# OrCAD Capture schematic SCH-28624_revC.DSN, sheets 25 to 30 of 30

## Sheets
25 25 Core Pwr: size B
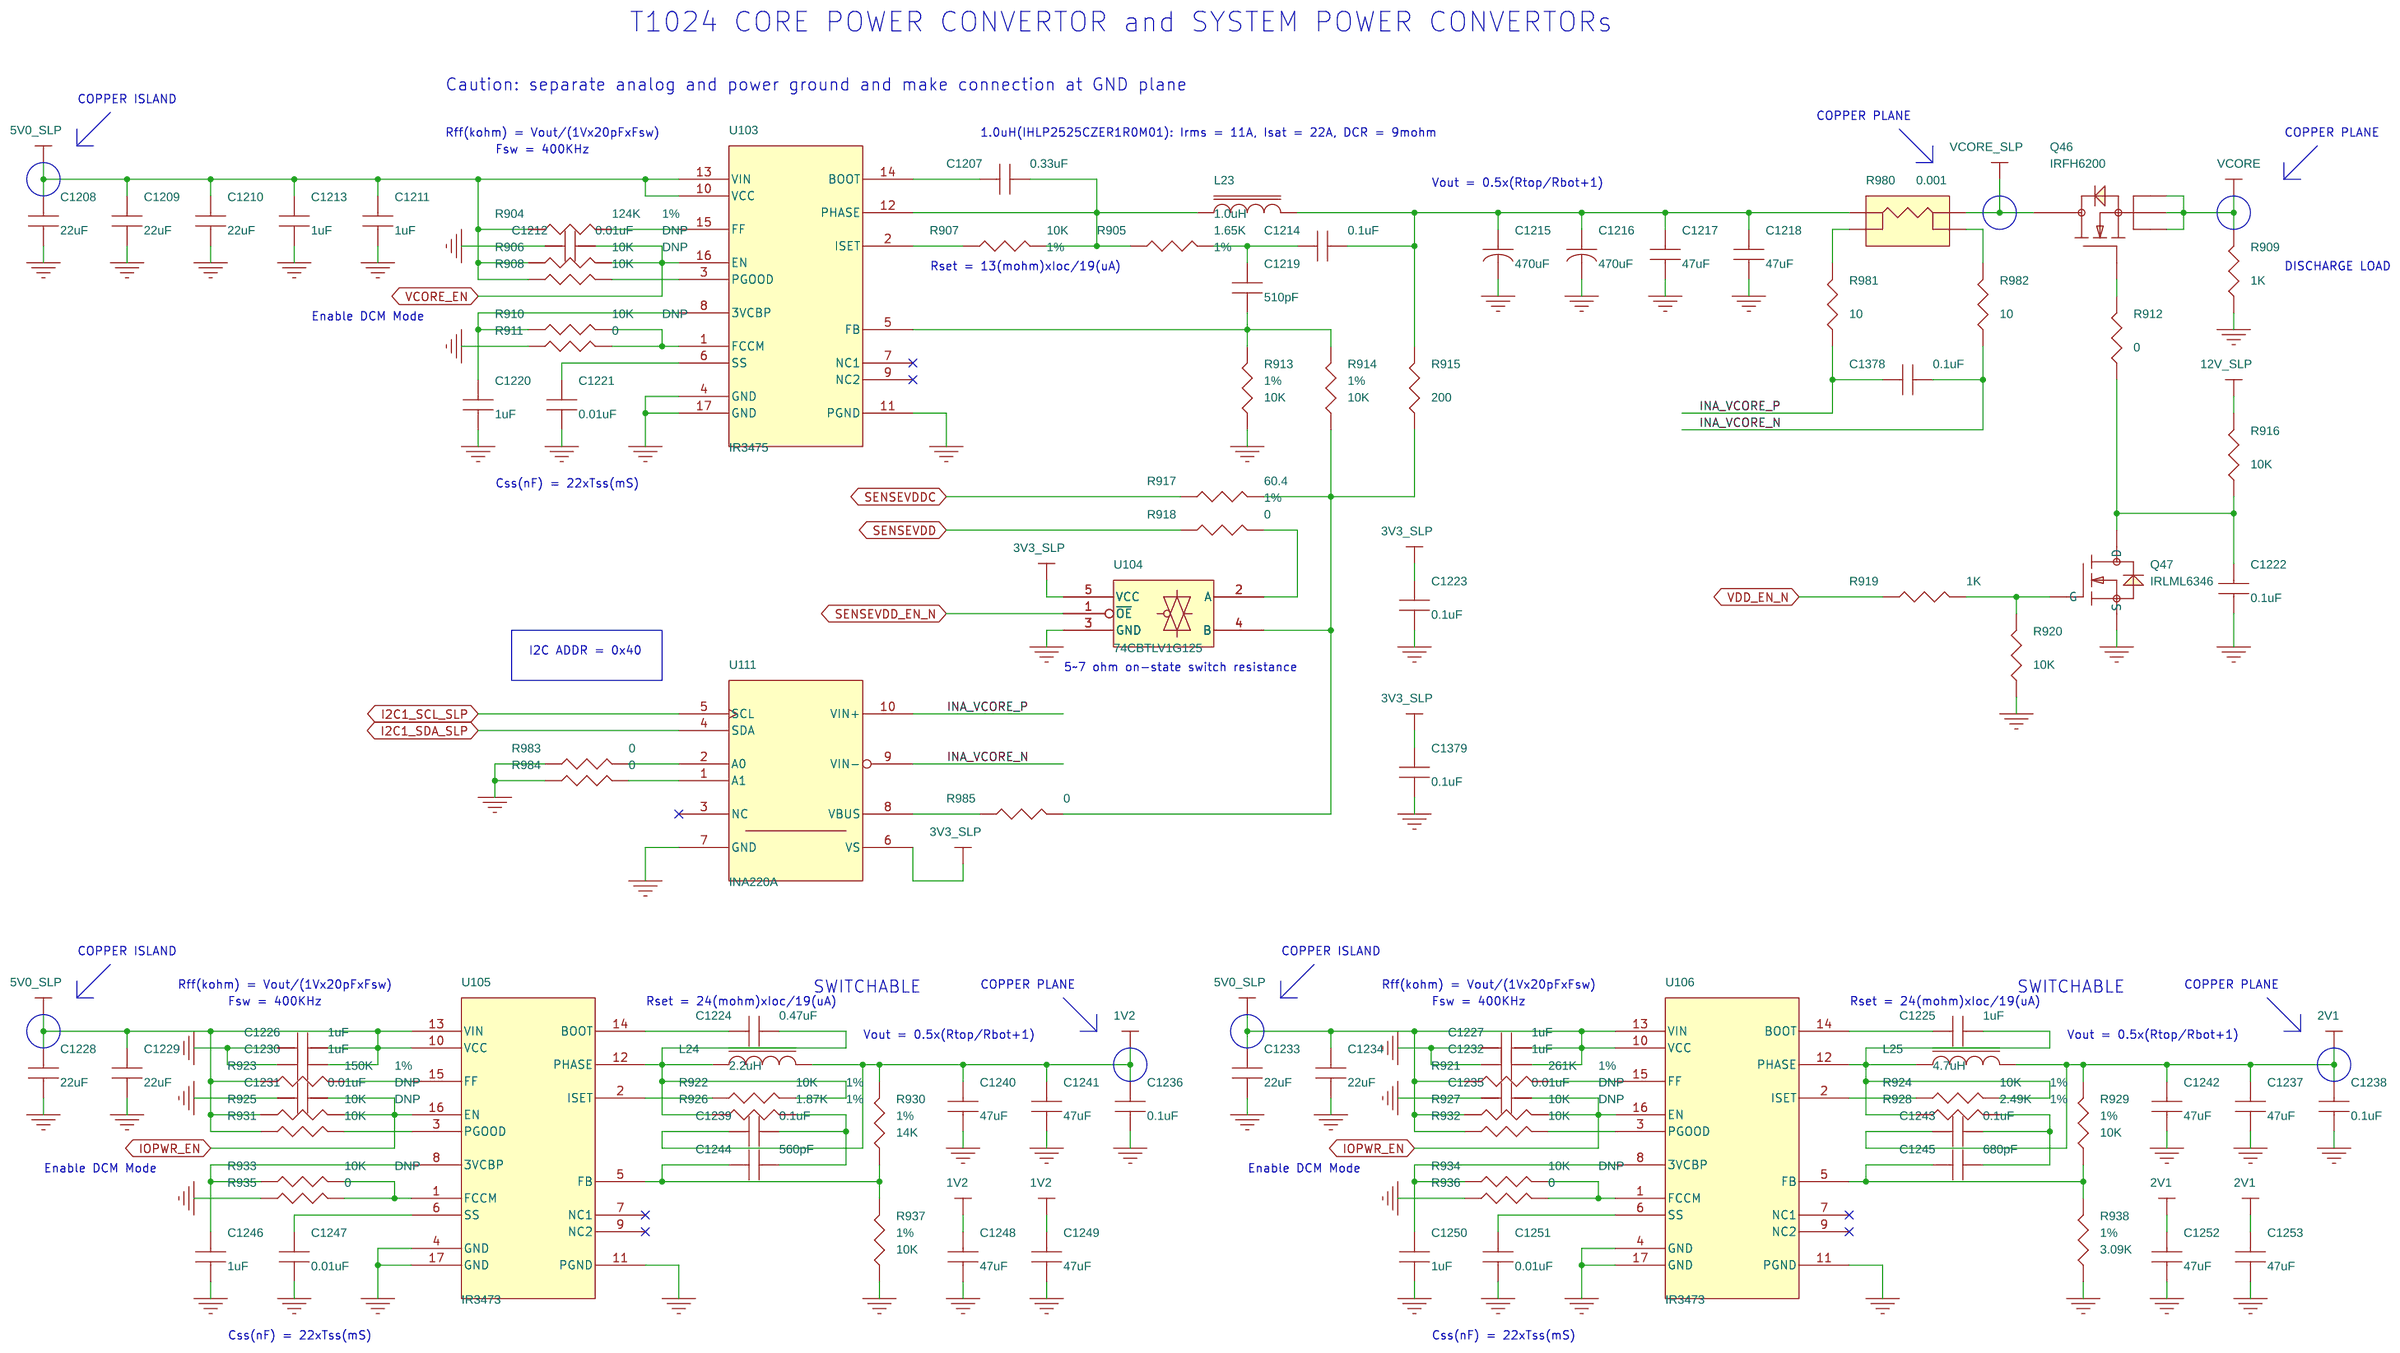
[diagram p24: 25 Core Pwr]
26 26 Other Pwr: size B
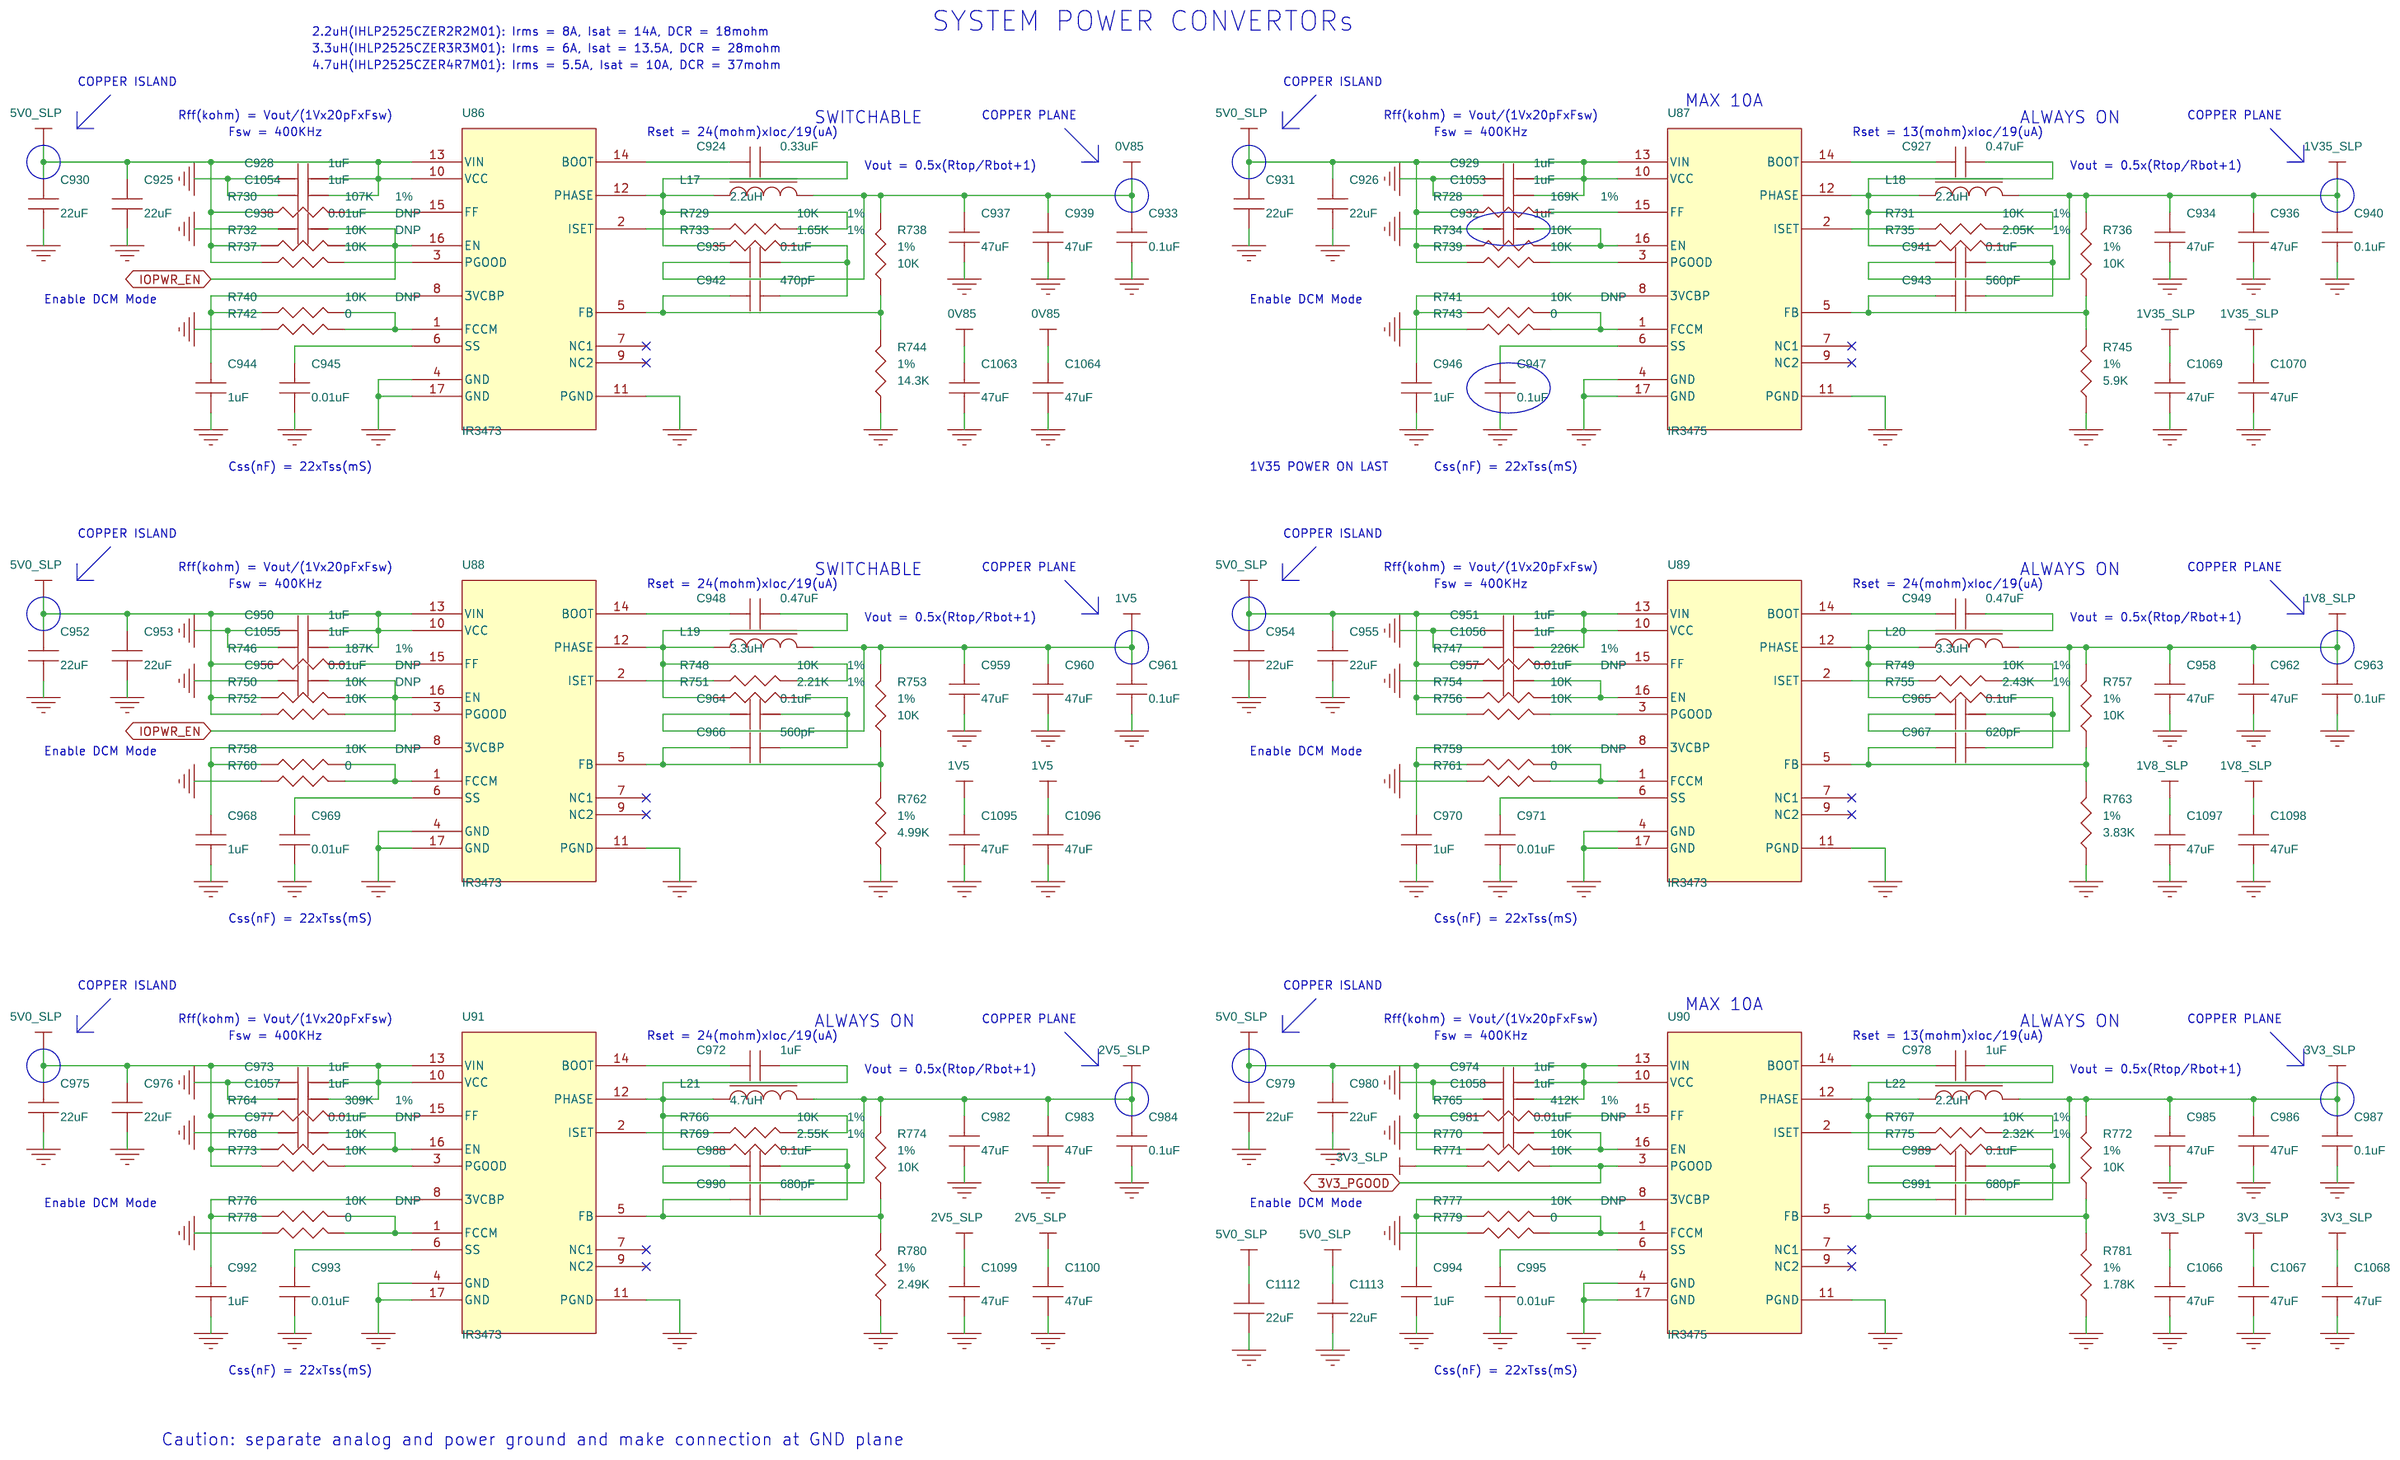
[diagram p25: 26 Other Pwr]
27 27 Pwr Switch: size B
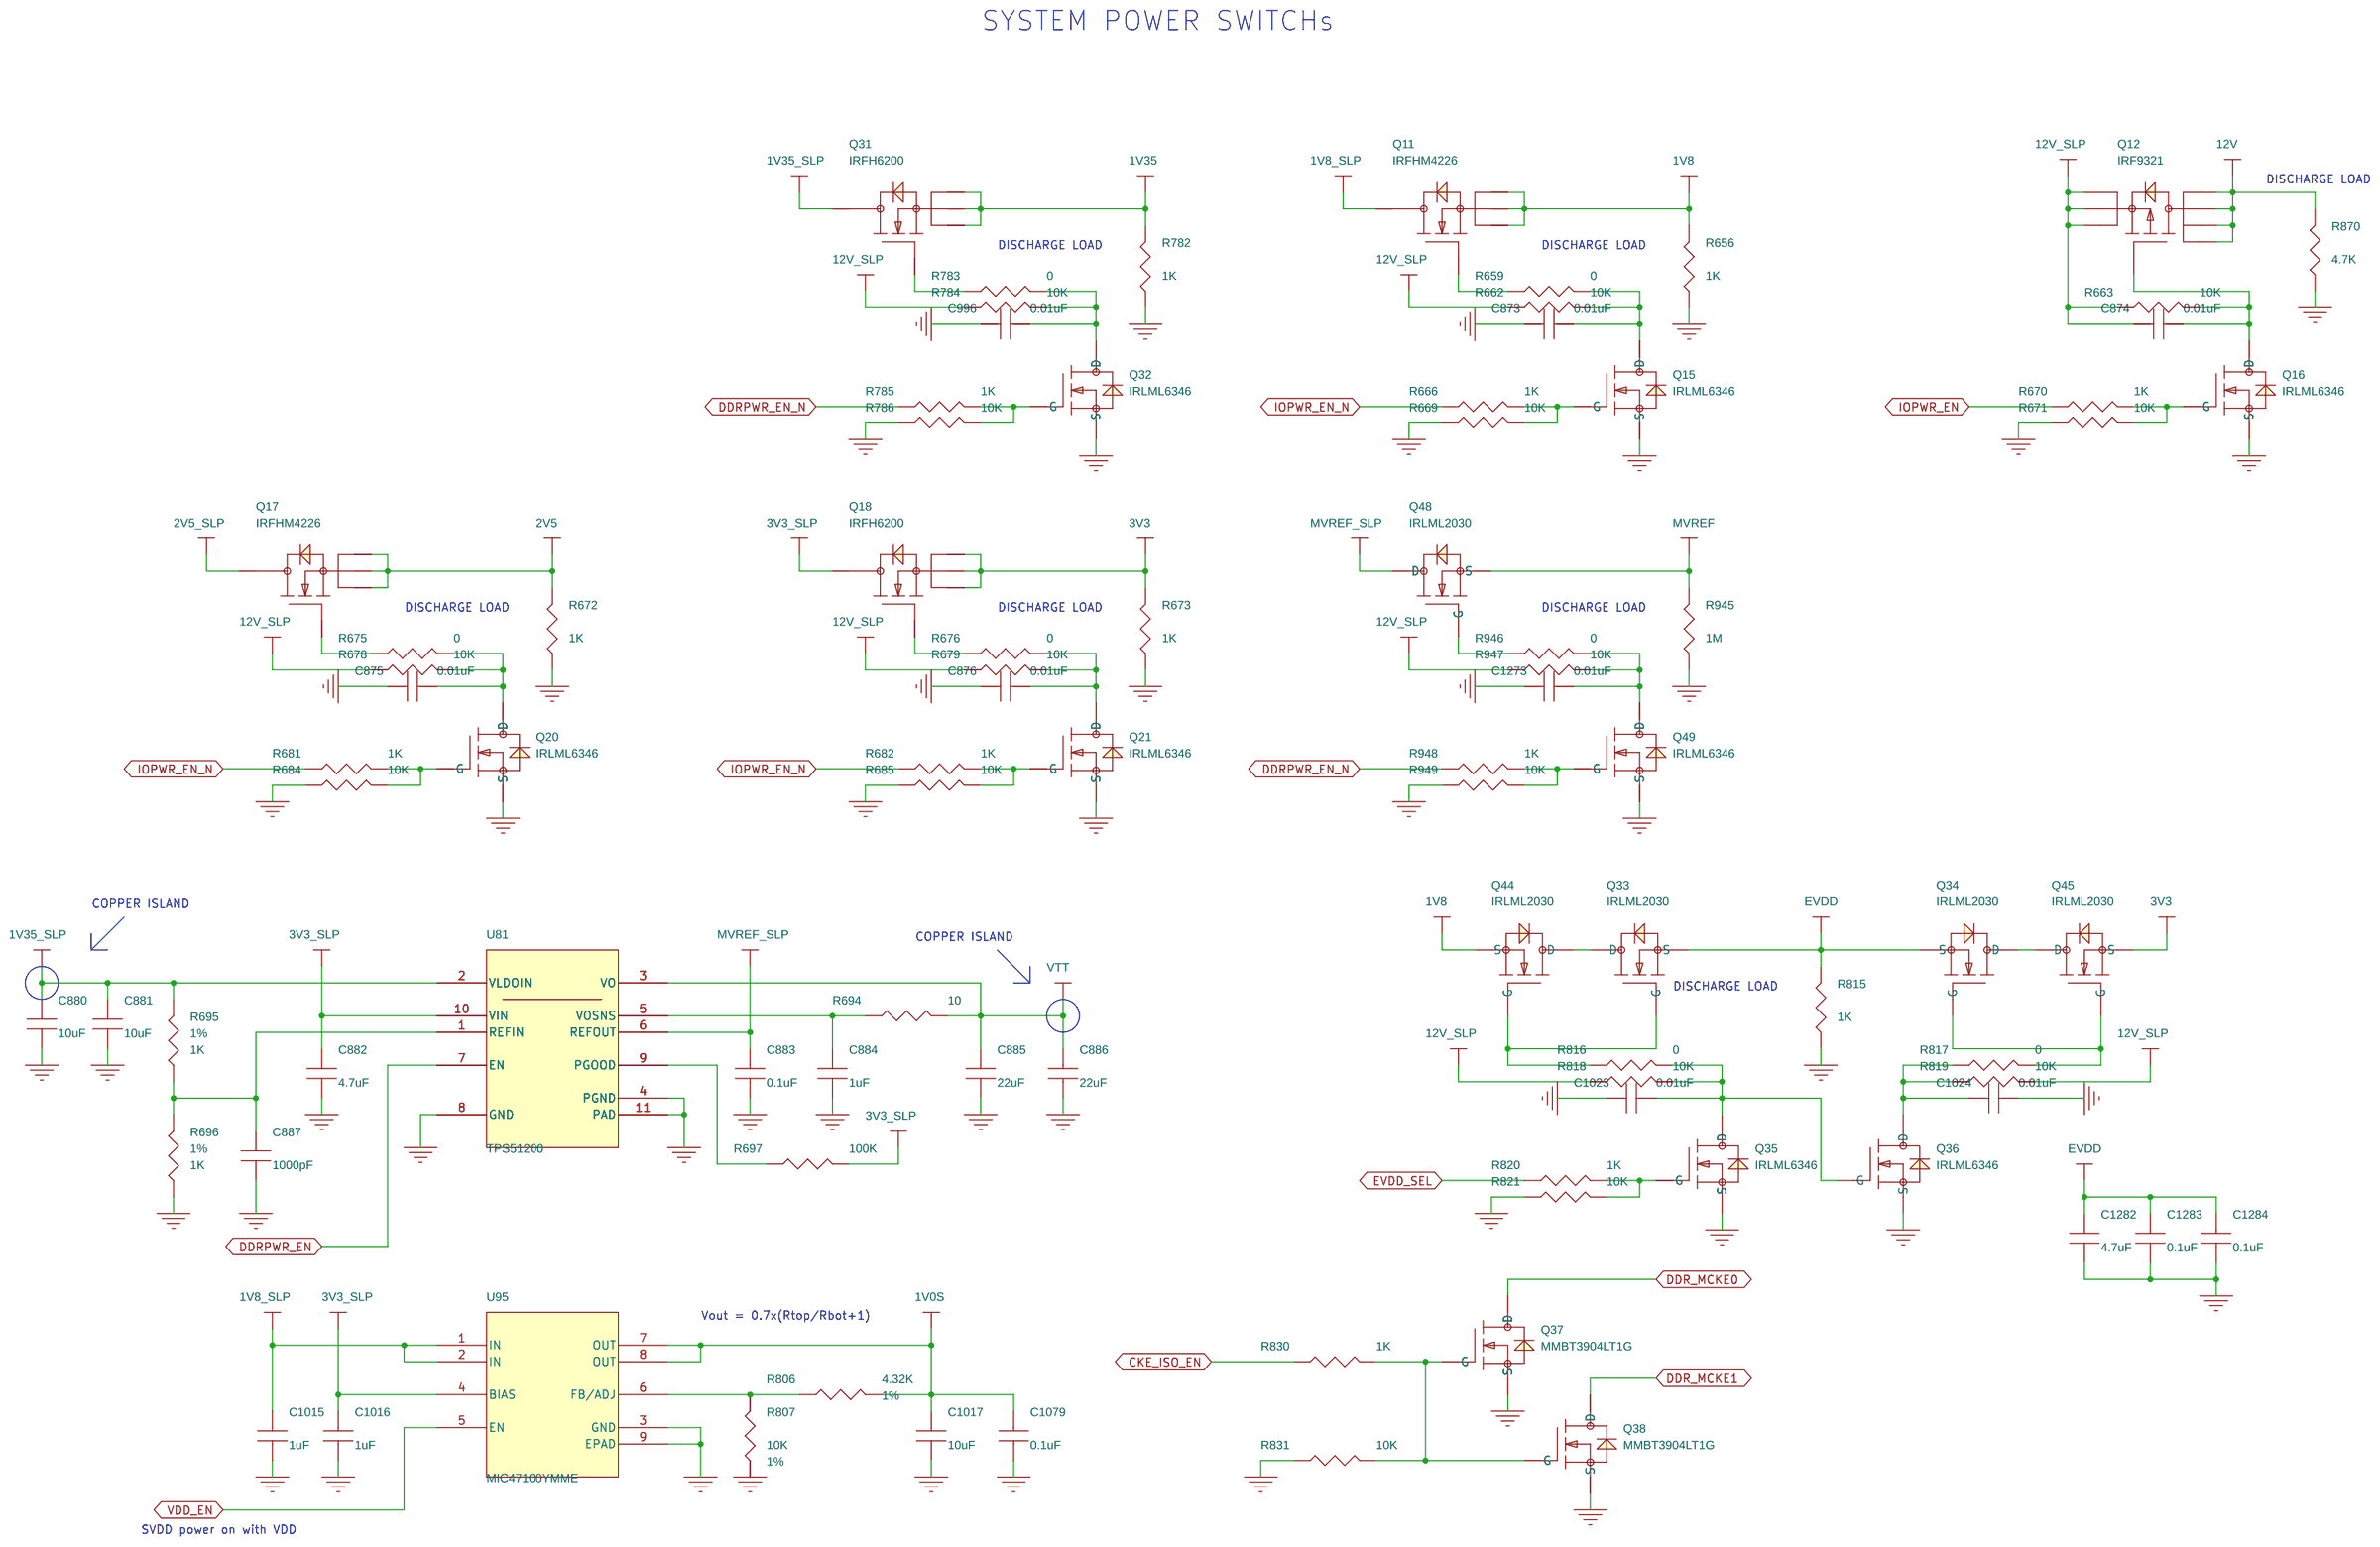
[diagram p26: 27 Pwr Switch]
28 28 Pwr In: size B
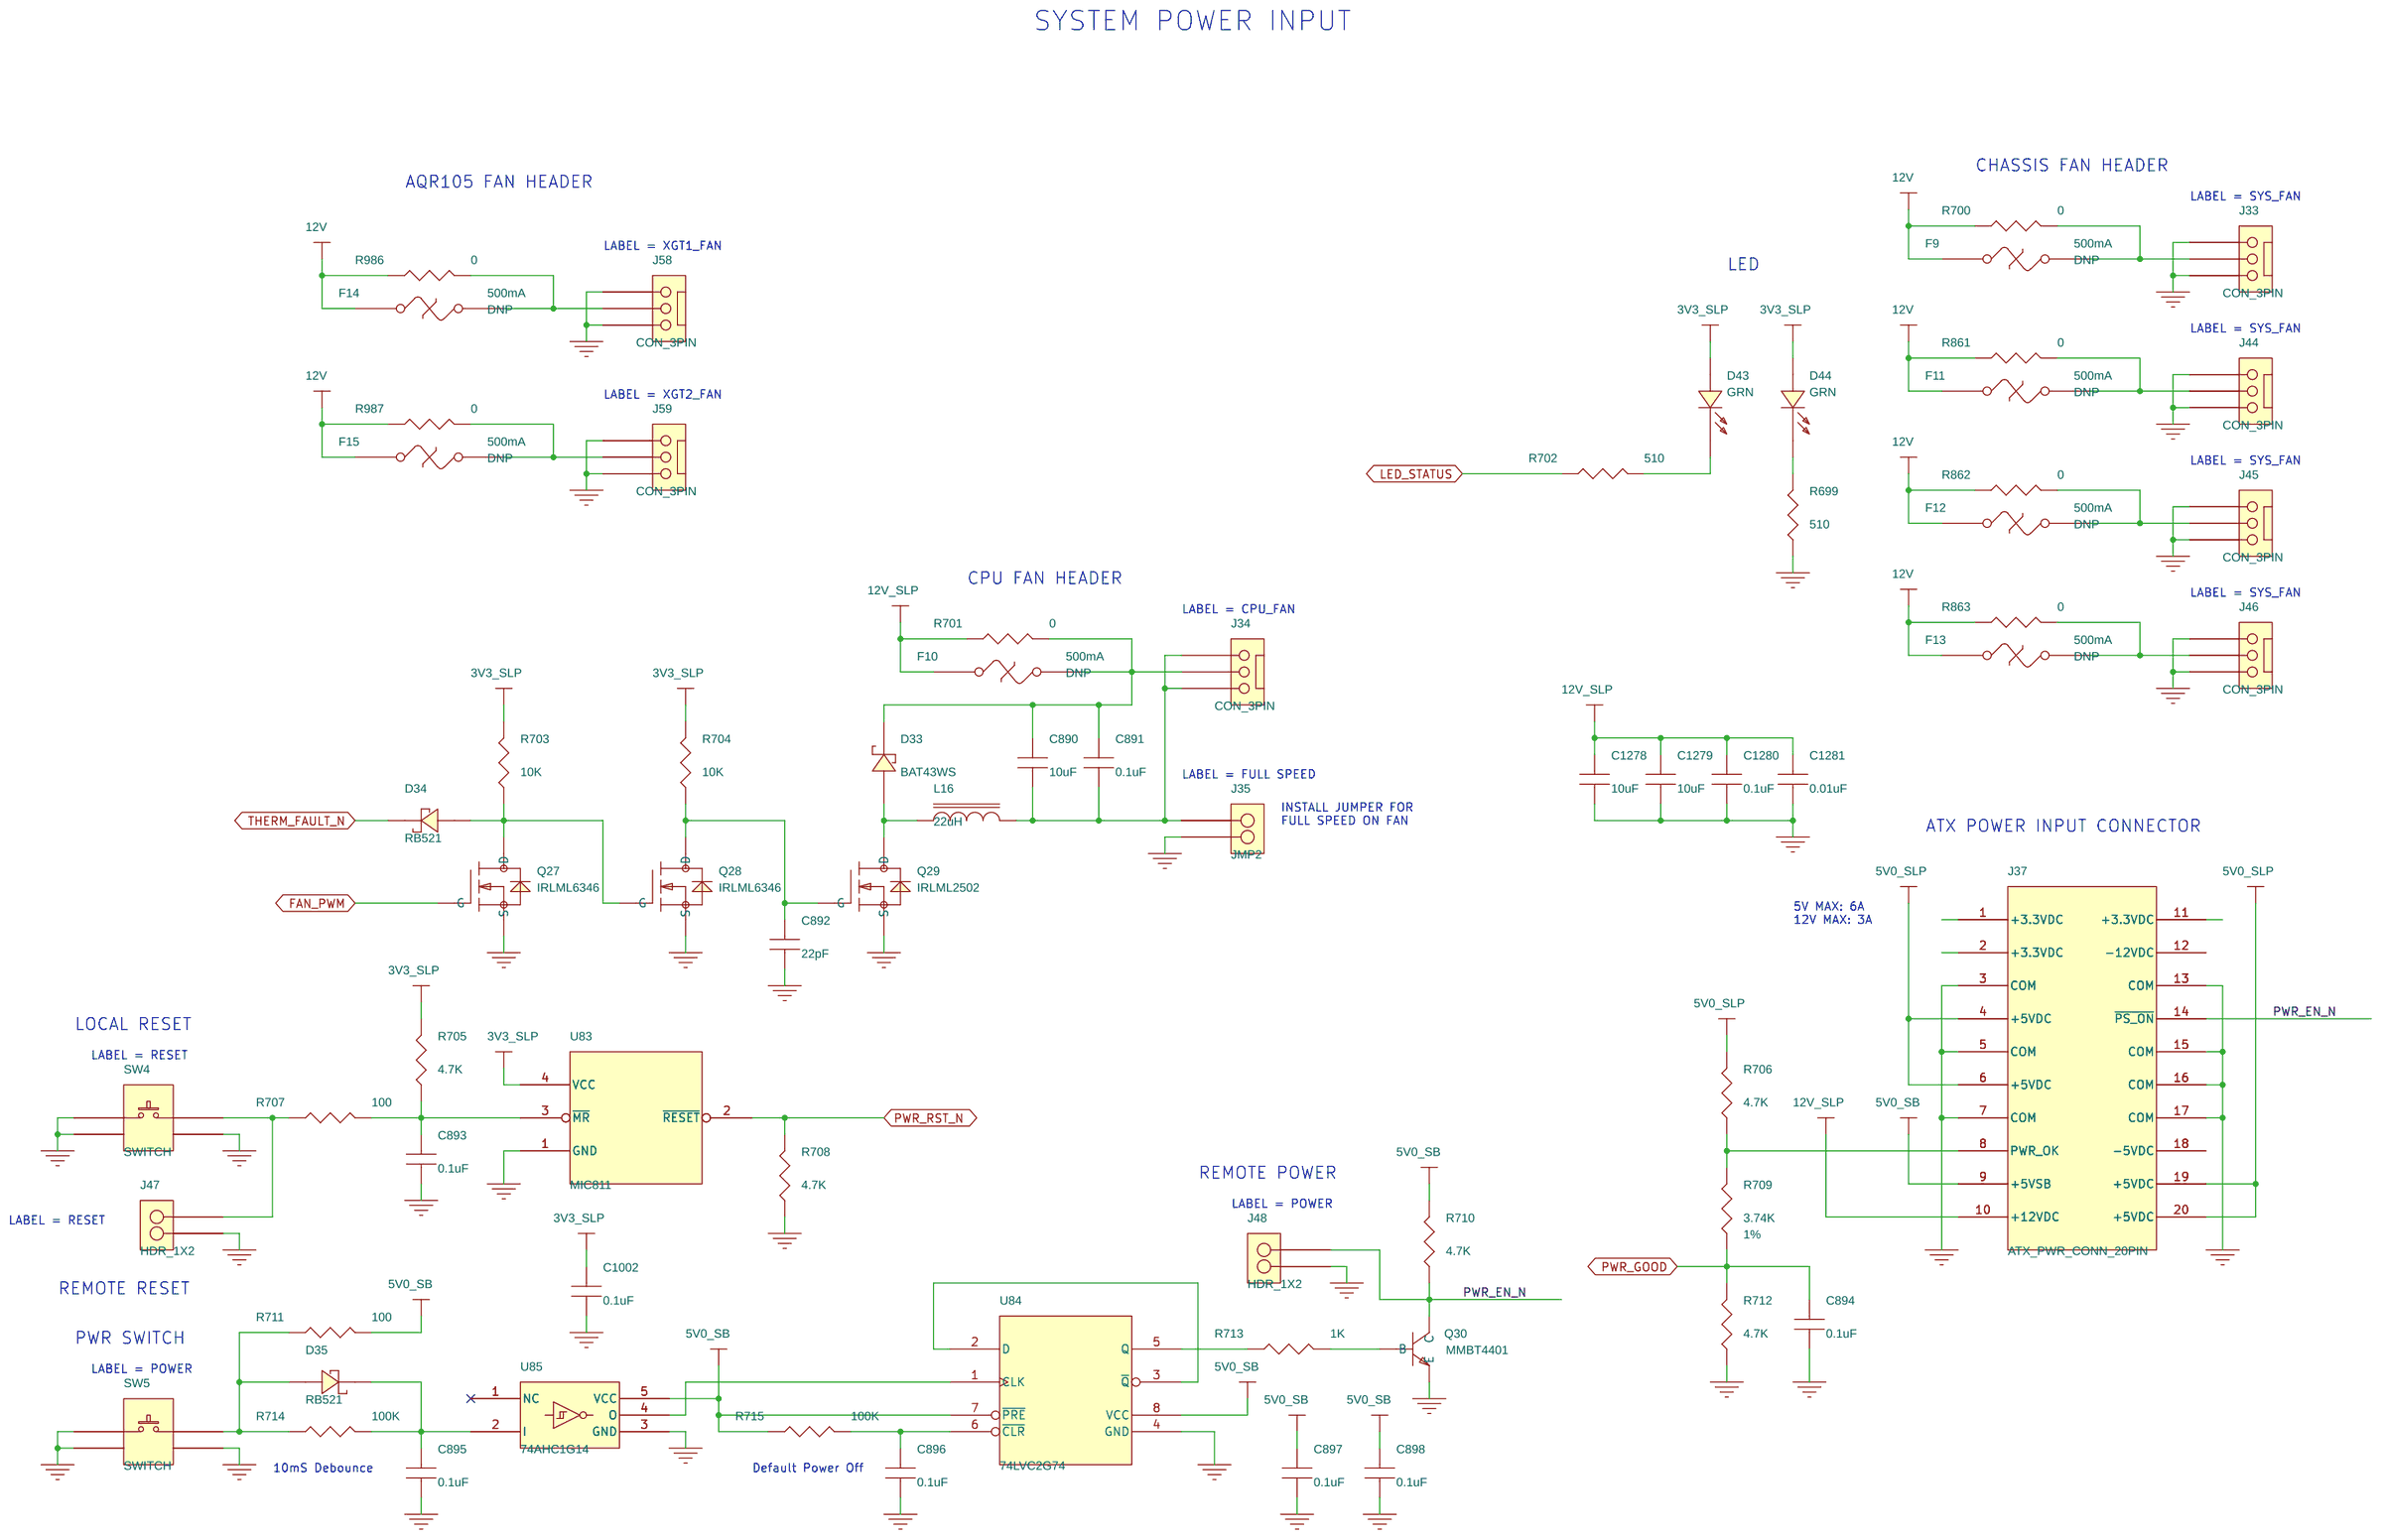
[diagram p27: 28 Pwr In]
29 29 MEC: size B
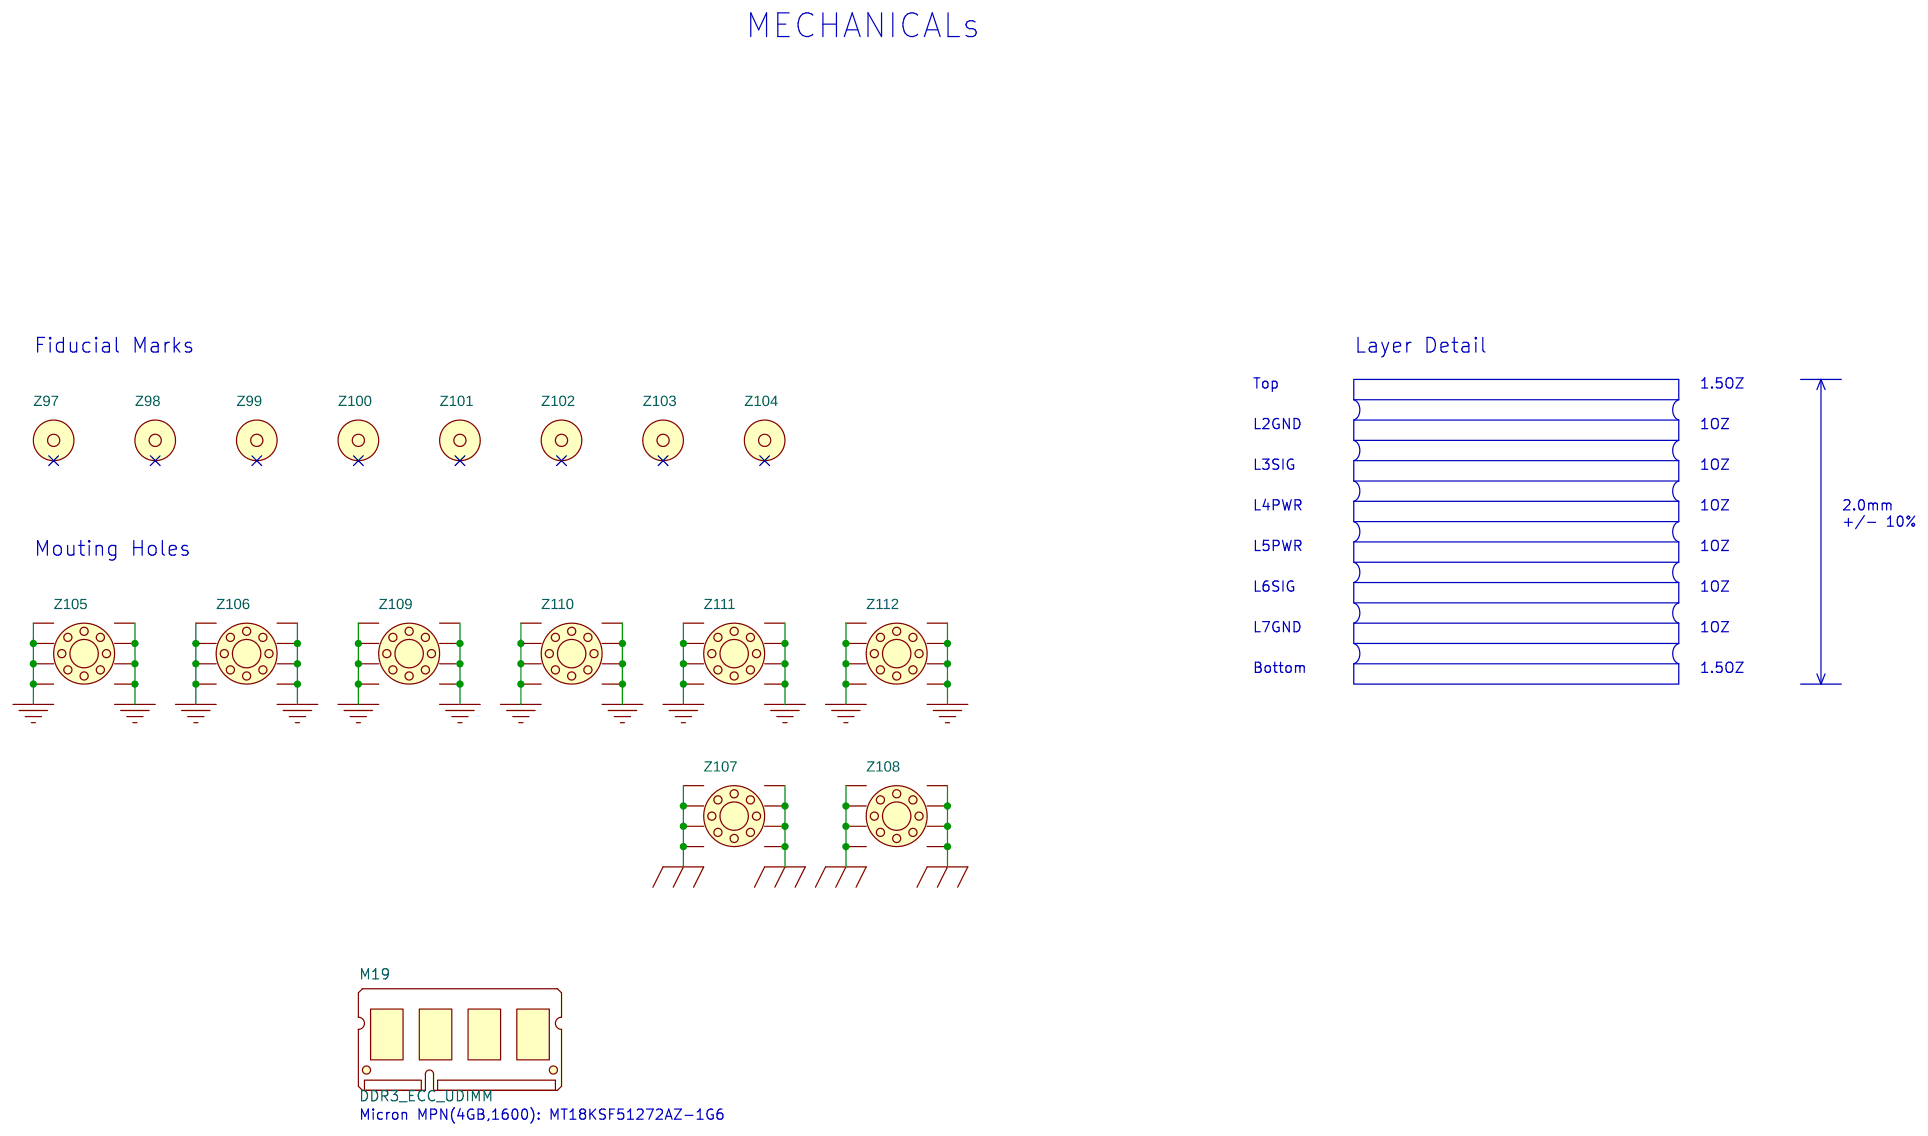
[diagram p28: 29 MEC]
30 30 Change List
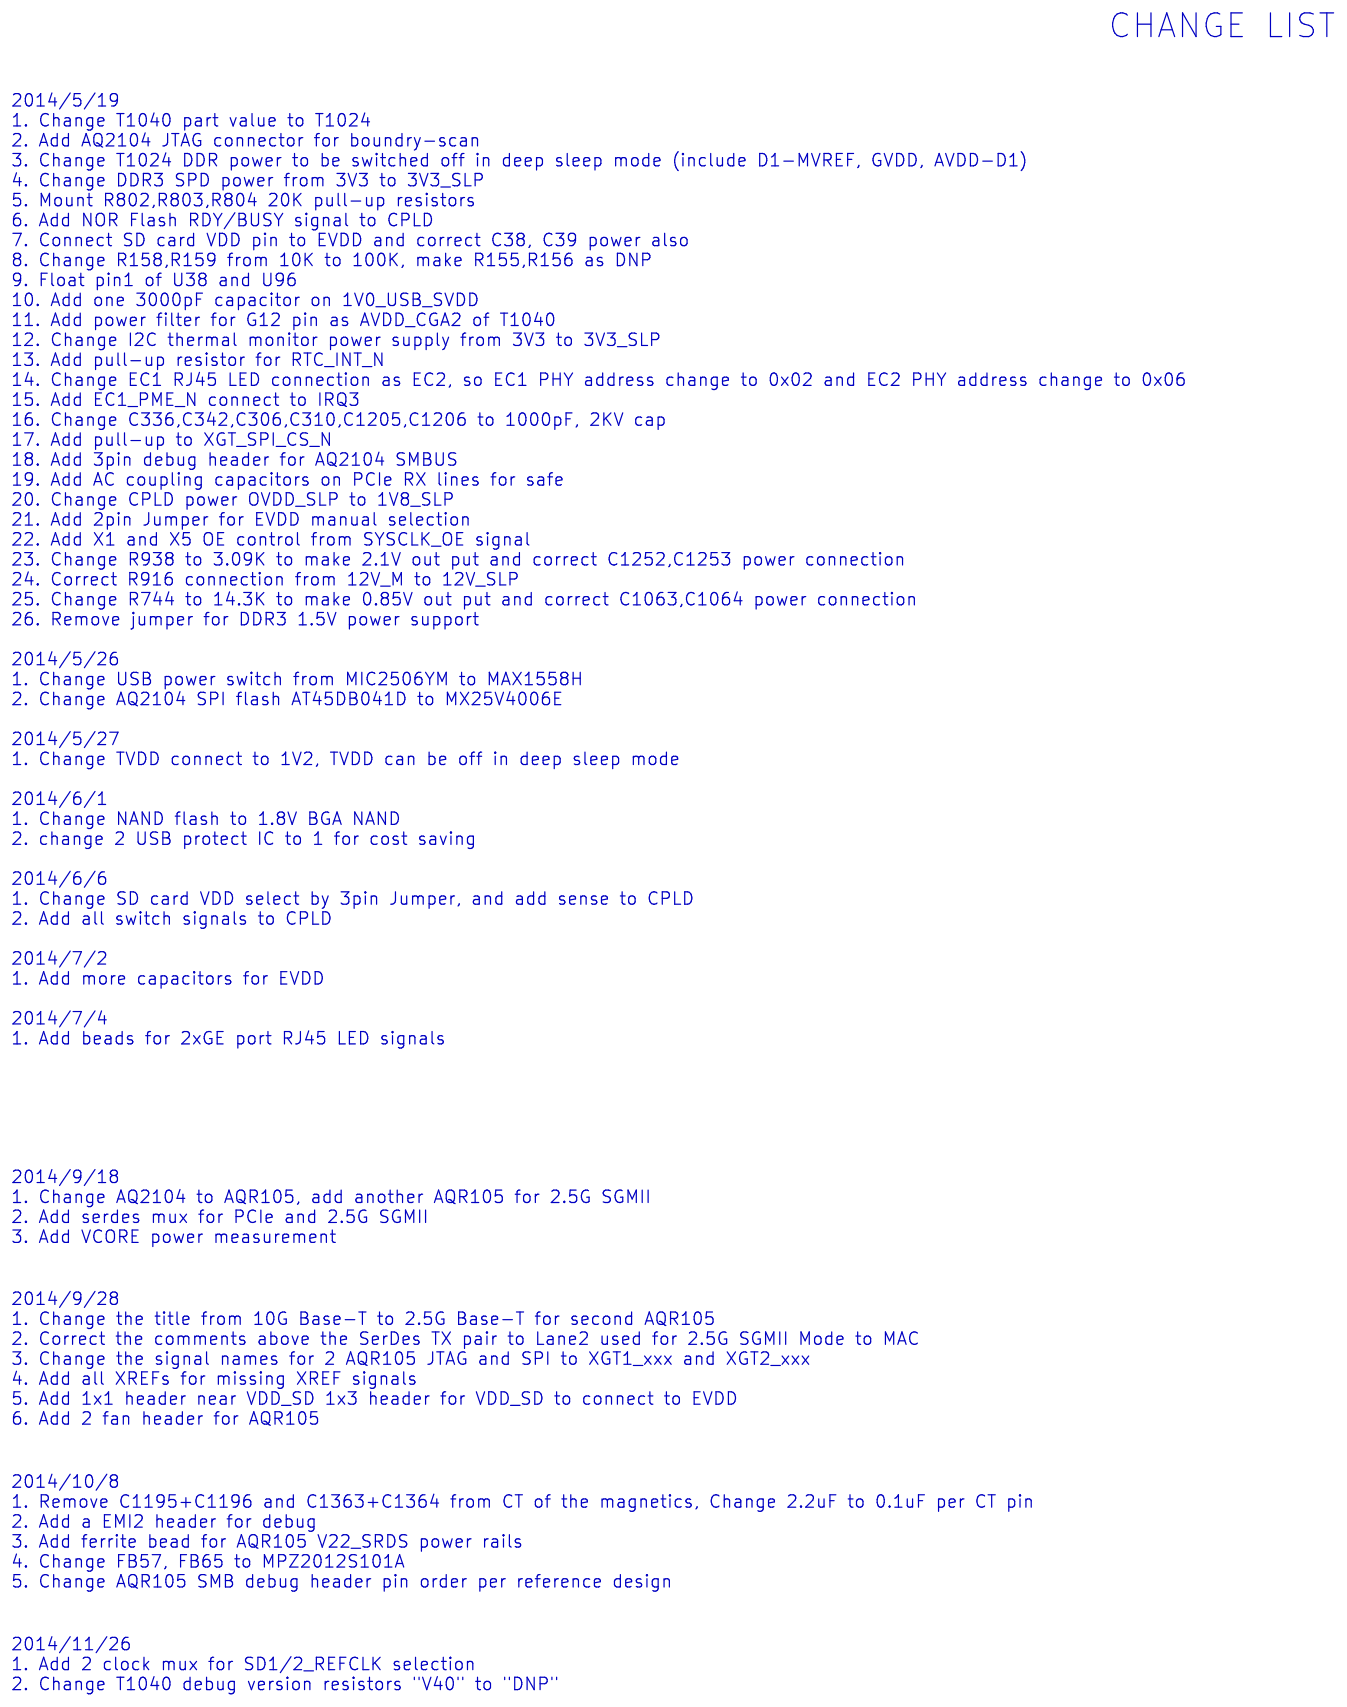
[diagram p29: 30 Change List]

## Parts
sheet 25 Core Pwr
C1207  0.33uF  [0603]
C1208  22uF  [1206]
C1209  22uF  [1206]
C1210  22uF  [1206]
C1211  1uF  [0603]
C1212  0.01uF  [0402]
C1213  1uF  [0603]
C1214  0.1uF  [0402]
C1215  470uF  [7343]
C1216  470uF  [7343]
C1217  47uF  [0805]
C1218  47uF  [0805]
C1219  510pF  [0402]
C1220  1uF  [0402]
C1221  0.01uF  [0402]
C1222  0.1uF  [0402]
C1223  0.1uF  [0402]
C1224  0.47uF  [0603]
C1225  1uF  [0603]
C1226  1uF  [0603]
C1227  1uF  [0603]
C1228  22uF  [1206]
C1229  22uF  [1206]
C1230  1uF  [0603]
C1231  0.01uF  [0402]
C1232  1uF  [0603]
C1233  22uF  [1206]
C1234  22uF  [1206]
C1235  0.01uF  [0402]
C1236  0.1uF  [0402]
C1237  47uF  [0805]
C1238  0.1uF  [0402]
C1239  0.1uF  [0402]
C1240  47uF  [0805]
C1241  47uF  [0805]
C1242  47uF  [0805]
C1243  0.1uF  [0402]
C1244  560pF  [0402]
C1245  680pF  [0402]
C1246  1uF  [0402]
C1247  0.01uF  [0402]
C1248  47uF  [0805]
C1249  47uF  [0805]
C1250  1uF  [0402]
C1251  0.01uF  [0402]
C1252  47uF  [0805]
C1253  47uF  [0805]
C1378  0.1uF  [0402]
C1379  0.1uF  [0402]
L23  1.0uH  [ind_ihlp_4040]
L24  2.2uH  [ind_ihlp_2525]
L25  4.7uH  [ind_ihlp_2525]
Q46  IRFH6200  [so_8_fl]
Q47  IRLML6346  [sot23]
R904  124K  [0402]
R905  1.65K  [0402]
R906  10K  [0402]
R907  10K  [0402]
R908  10K  [0402]
R909  1K  [0402]
R910  10K  [0402]
R911  0  [0402]
R912  0  [0402]
R913  10K  [0402]
R914  10K  [0402]
R915  200  [0402]
R916  10K  [0402]
R917  60.4  [0402]
R918  0  [0402]
R919  1K  [0402]
R920  10K  [0402]
R921  261K  [0402]
R922  10K  [0402]
R923  150K  [0402]
R924  10K  [0402]
R925  10K  [0402]
R926  1.87K  [0402]
R927  10K  [0402]
R928  2.49K  [0402]
R929  10K  [0402]
R930  14K  [0402]
R931  10K  [0402]
R932  10K  [0402]
R933  10K  [0402]
R934  10K  [0402]
R935  0  [0402]
R936  0  [0402]
R937  10K  [0402]
R938  3.09K  [0402]
R980  0.001  [res_wsl2726]
R981  10  [0402]
R982  10  [0402]
R983  0  [0402]
R984  0  [0402]
R985  0  [0402]
U103  IR3475  [qfn_supirbuck_4x5]
U104  74CBTLV1G125  [sc70_5]
U105  IR3473  [qfn_supirbuck_4x5]
U106  IR3473  [qfn_supirbuck_4x5]
U111  INA220A  [msop_10]
sheet 26 Other Pwr
C924  0.33uF  [0603]
C925  22uF  [1206]
C926  22uF  [1206]
C927  0.47uF  [0603]
C928  1uF  [0603]
C929  1uF  [0603]
C930  22uF  [1206]
C931  22uF  [1206]
C932  1uF  [0402]
C933  0.1uF  [0402]
C934  47uF  [0805]
C935  0.1uF  [0402]
C936  47uF  [0805]
C937  47uF  [0805]
C938  0.01uF  [0402]
C939  47uF  [0805]
C940  0.1uF  [0402]
C941  0.1uF  [0402]
C942  470pF  [0402]
C943  560pF  [0402]
C944  1uF  [0402]
C945  0.01uF  [0402]
C946  1uF  [0402]
C947  0.1uF  [0402]
C948  0.47uF  [0603]
C949  0.47uF  [0603]
C950  1uF  [0603]
C951  1uF  [0603]
C952  22uF  [1206]
C953  22uF  [1206]
C954  22uF  [1206]
C955  22uF  [1206]
C956  0.01uF  [0402]
C957  0.01uF  [0402]
C958  47uF  [0805]
C959  47uF  [0805]
C960  47uF  [0805]
C961  0.1uF  [0402]
C962  47uF  [0805]
C963  0.1uF  [0402]
C964  0.1uF  [0402]
C965  0.1uF  [0402]
C966  560pF  [0402]
C967  620pF  [0402]
C968  1uF  [0402]
C969  0.01uF  [0402]
C970  1uF  [0402]
C971  0.01uF  [0402]
C972  1uF  [0603]
C973  1uF  [0603]
C974  1uF  [0603]
C975  22uF  [1206]
C976  22uF  [1206]
C977  0.01uF  [0402]
C978  1uF  [0603]
C979  22uF  [1206]
C980  22uF  [1206]
C981  0.01uF  [0402]
C982  47uF  [0805]
C983  47uF  [0805]
C984  0.1uF  [0402]
C985  47uF  [0805]
C986  47uF  [0805]
C987  0.1uF  [0402]
C988  0.1uF  [0402]
C989  0.1uF  [0402]
C990  680pF  [0402]
C991  680pF  [0402]
C992  1uF  [0402]
C993  0.01uF  [0402]
C994  1uF  [0402]
C995  0.01uF  [0402]
C1053  1uF  [0603]
C1054  1uF  [0603]
C1055  1uF  [0603]
C1056  1uF  [0603]
C1057  1uF  [0603]
C1058  1uF  [0603]
C1063  47uF  [0805]
C1064  47uF  [0805]
C1066  47uF  [0805]
C1067  47uF  [0805]
C1068  47uF  [0805]
C1069  47uF  [0805]
C1070  47uF  [0805]
C1095  47uF  [0805]
C1096  47uF  [0805]
C1097  47uF  [0805]
C1098  47uF  [0805]
C1099  47uF  [0805]
C1100  47uF  [0805]
C1112  22uF  [1206]
C1113  22uF  [1206]
L17  2.2uH  [ind_ihlp_2525]
L18  2.2uH  [ind_ihlp_2525]
L19  3.3uH  [ind_ihlp_2525]
L20  3.3uH  [ind_ihlp_2525]
L21  4.7uH  [ind_ihlp_2525]
L22  2.2uH  [ind_ihlp_2525]
R728  169K  [0402]
R729  10K  [0402]
R730  107K  [0402]
R731  10K  [0402]
R732  10K  [0402]
R733  1.65K  [0402]
R734  10K  [0402]
R735  2.05K  [0402]
R736  10K  [0402]
R737  10K  [0402]
R738  10K  [0402]
R739  10K  [0402]
R740  10K  [0402]
R741  10K  [0402]
R742  0  [0402]
R743  0  [0402]
R744  14.3K  [0402]
R745  5.9K  [0402]
R746  187K  [0402]
R747  226K  [0402]
R748  10K  [0402]
R749  10K  [0402]
R750  10K  [0402]
R751  2.21K  [0402]
R752  10K  [0402]
R753  10K  [0402]
R754  10K  [0402]
R755  2.43K  [0402]
R756  10K  [0402]
R757  10K  [0402]
R758  10K  [0402]
R759  10K  [0402]
R760  0  [0402]
R761  0  [0402]
R762  4.99K  [0402]
R763  3.83K  [0402]
R764  309K  [0402]
R765  412K  [0402]
R766  10K  [0402]
R767  10K  [0402]
R768  10K  [0402]
R769  2.55K  [0402]
R770  10K  [0402]
R771  10K  [0402]
R772  10K  [0402]
R773  10K  [0402]
R774  10K  [0402]
R775  2.32K  [0402]
R776  10K  [0402]
R777  10K  [0402]
R778  0  [0402]
R779  0  [0402]
R780  2.49K  [0402]
R781  1.78K  [0402]
U86  IR3473  [qfn_supirbuck_4x5]
U87  IR3475  [qfn_supirbuck_4x5]
U88  IR3473  [qfn_supirbuck_4x5]
U89  IR3473  [qfn_supirbuck_4x5]
U90  IR3475  [qfn_supirbuck_4x5]
U91  IR3473  [qfn_supirbuck_4x5]
sheet 27 Pwr Switch
C873  0.01uF  [0402]
C874  0.01uF  [0402]
C875  0.01uF  [0402]
C876  0.01uF  [0402]
C880  10uF  [0603]
C881  10uF  [0603]
C882  4.7uF  [0603]
C883  0.1uF  [0402]
C884  1uF  [0402]
C885  22uF  [0805]
C886  22uF  [0805]
C887  1000pF  [0402]
C996  0.01uF  [0402]
C1015  1uF  [0402]
C1016  1uF  [0402]
C1017  10uF  [0603]
C1023  0.01uF  [0402]
C1024  0.01uF  [0402]
C1079  0.1uF  [0402]
C1273  0.01uF  [0402]
C1282  4.7uF  [0603]
C1283  0.1uF  [0402]
C1284  0.1uF  [0402]
Q11  IRFHM4226  [u8_fl]
Q12  IRF9321  [so_8]
Q15  IRLML6346  [sot23]
Q16  IRLML6346  [sot23]
Q17  IRFHM4226  [u8_fl]
Q18  IRFH6200  [so_8_fl]
Q20  IRLML6346  [sot23]
Q21  IRLML6346  [sot23]
Q31  IRFH6200  [so_8_fl]
Q32  IRLML6346  [sot23]
Q33  IRLML2030  [sot23]
Q34  IRLML2030  [sot23]
Q35  IRLML6346  [sot23]
Q36  IRLML6346  [sot23]
Q37  MMBT3904LT1G  [sot23]
Q38  MMBT3904LT1G  [sot23]
Q44  IRLML2030  [sot23]
Q45  IRLML2030  [sot23]
Q48  IRLML2030  [sot23]
Q49  IRLML6346  [sot23]
R656  1K  [0402]
R659  0  [0402]
R662  10K  [0402]
R663  10K  [0402]
R666  1K  [0402]
R669  10K  [0402]
R670  1K  [0402]
R671  10K  [0402]
R672  1K  [0402]
R673  1K  [0402]
R675  0  [0402]
R676  0  [0402]
R678  10K  [0402]
R679  10K  [0402]
R681  1K  [0402]
R682  1K  [0402]
R684  10K  [0402]
R685  10K  [0402]
R694  10  [0402]
R695  1K  [0402]
R696  1K  [0402]
R697  100K  [0402]
R782  1K  [0402]
R783  0  [0402]
R784  10K  [0402]
R785  1K  [0402]
R786  10K  [0402]
R806  4.32K  [0402]
R807  10K  [0402]
R815  1K  [0402]
R816  0  [0402]
R817  0  [0402]
R818  10K  [0402]
R819  10K  [0402]
R820  1K  [0402]
R821  10K  [0402]
R830  1K  [0402]
R831  10K  [0402]
R870  4.7K  [0402]
R945  1M  [0402]
R946  0  [0402]
R947  10K  [0402]
R948  1K  [0402]
R949  10K  [0402]
U81  TPS51200  [dfn_p050_d040_b300_10_e240x165]
U95  MIC47100YMME  [msop_8_e170]
sheet 28 Pwr In
C890  10uF  [1206]
C891  0.1uF  [0603]
C892  22pF  [0402]
C893  0.1uF  [0402]
C894  0.1uF  [0402]
C895  0.1uF  [0402]
C896  0.1uF  [0402]
C897  0.1uF  [0402]
C898  0.1uF  [0402]
C1002  0.1uF  [0402]
C1278  10uF  [1206]
C1279  10uF  [1206]
C1280  0.1uF  [0603]
C1281  0.01uF  [0402]
D33  BAT43WS  [sod323]
D34  RB521  [sod523]
D35  RB521  [sod523]
D43  GRN  [led_pm_1s]
D44  GRN  [led_pm_1s]
F9  500mA  [1206]
F10  500mA  [1206]
F11  500mA  [1206]
F12  500mA  [1206]
F13  500mA  [1206]
F14  500mA  [1206]
F15  500mA  [1206]
J33  CON_3PIN  [con_wafer_p254_s_1x3]
J34  CON_3PIN  [con_wafer_p254_s_1x3]
J35  JMP2  [jmp_p254_t_1x2]
J37  ATX_PWR_CONN_20PIN  [con_atx_20pin]
J44  CON_3PIN  [con_wafer_p254_s_1x3]
J45  CON_3PIN  [con_wafer_p254_s_1x3]
J46  CON_3PIN  [con_wafer_p254_s_1x3]
J47  HDR_1X2  [jmp_p254_t_1x2]
J48  HDR_1X2  [jmp_p254_t_1x2]
J58  CON_3PIN  [con_wafer_p254_s_1x3]
J59  CON_3PIN  [con_wafer_p254_s_1x3]
L16  22uH  [ind_45x40]
Q27  IRLML6346  [sot23]
Q28  IRLML6346  [sot23]
Q29  IRLML2502  [sot23]
Q30  MMBT4401  [sot23]
R699  510  [0402]
R700  0  [1206]
R701  0  [1206]
R702  510  [0402]
R703  10K  [0402]
R704  10K  [0402]
R705  4.7K  [0402]
R706  4.7K  [0402]
R707  100  [0402]
R708  4.7K  [0402]
R709  3.74K  [0402]
R710  4.7K  [0402]
R711  100  [0402]
R712  4.7K  [0402]
R713  1K  [0402]
R714  100K  [0402]
R715  100K  [0402]
R861  0  [1206]
R862  0  [1206]
R863  0  [1206]
R986  0  [1206]
R987  0  [1206]
SW4  SWITCH  [con_sw_60x60_2p2_34]
SW5  SWITCH  [con_sw_60x60_2p2_34]
U83  MIC811  [sot143]
U84  74LVC2G74  [u8]
U85  74AHC1G14  [sc70_5]
sheet 29 MEC
M19  DDR3_ECC_UDIMM  [none]
Z97  FIDUCIAL  [fiducial]
Z98  FIDUCIAL  [fiducial]
Z99  FIDUCIAL  [fiducial]
Z100  FIDUCIAL  [fiducial]
Z101  FIDUCIAL  [fiducial]
Z102  FIDUCIAL  [fiducial]
Z103  FIDUCIAL  [fiducial]
Z104  FIDUCIAL  [fiducial]
Z105  MH_M8  [mh_900c400n_m]
Z106  MH_M8  [mh_900c400n_m]
Z107  MH_M8  [mh_900c400n_m]
Z108  MH_M8  [mh_900c400n_m]
Z109  MH_M8  [mh_900c400n_m]
Z110  MH_M8  [mh_900c400n_m]
Z111  MH_M8  [mh_900c400n_m]
Z112  MH_M8  [mh_900c400n_m]

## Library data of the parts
C924 C1207 = CAP: AGILE_PN: 150-00077; VOLTAGE: 16V
C925 C926 C930 C931 C952-C955 C975 C976 C979 C980 C1112 C1113 C1208-C1210 C1228 C1229 C1233 C1234 = CAP: AGILE_PN: 150-77933; VOLTAGE: 16V
C928 C929 C950 C951 C972-C974 C978 C1053-C1058 C1211 C1213 C1225-C1227 C1230 C1232 = CAP: AGILE_PN: 150-30124; VOLTAGE: 16V
C938 C956 C957 C977 C981 C1212 C1231 C1235 = CAP: BOM_IGNORE: DNP; VOLTAGE: 25V
C883 C893-C898 C933 C935 C940 C941 C947 C961 C963-C965 C984 C987-C989 C1002 C1079 C1214 C1222 C1223 C1236 C1238 C1239 C1243 C1283 C1284 C1378 C1379 = CAP: AGILE_PN: 150-75663; VOLTAGE: 16V
C1215 C1216 = CAP_E: AGILE_PN: 150-00086; MPN: 2R5TPE470M7; TYPE: CAP; VOLTAGE: 2.5V; Vendor: SANYO
C934 C936 C937 C939 C958-C960 C962 C982 C983 C985 C986 C1063 C1064 C1066-C1070 C1095-C1100 C1217 C1218 C1237 C1240-C1242 C1248 C1249 C1252 C1253 = CAP: AGILE_PN: 150-79458; VOLTAGE: 6.3V
C1219 = CAP: AGILE_PN: 150-00080; VOLTAGE: 50V
C884 C932 C944 C946 C968 C970 C992 C994 C1015 C1016 C1220 C1246 C1250 = CAP: AGILE_PN: 150-75421; VOLTAGE: 6.3V
C873-C876 C945 C969 C971 C993 C995 C996 C1023 C1024 C1221 C1247 C1251 C1273 C1281 = CAP: AGILE_PN: 150-75183; VOLTAGE: 25V
C927 C948 C949 C1224 = CAP: AGILE_PN: 150-30233; VOLTAGE: 16V
C943 C966 C1244 = CAP: AGILE_PN: 150-75679; VOLTAGE: 50V
C990 C991 C1245 = CAP: AGILE_PN: 150-00082; VOLTAGE: 50V
L23 = IND_IRON: AGILE_PN: 180-78322; MPN: IHLP4040DZER1R0M01; TYPE: IND; Vendor: Vishay
L17 L18 L22 L24 = IND_IRON: AGILE_PN: 180-75018; MPN: IHLP2525CZER2R2M01; TYPE: IND; Vendor: Vishay
L21 L25 = IND_IRON: AGILE_PN: 180-75111; MPN: IHLP2525CZER4R7M01; TYPE: IND; Vendor: Vishay
Q18 Q31 Q46 = NMOS_SO8FL: AGILE_PN: 480-78291; MPN: IRFH6200TRPBF; TYPE: MOS; Vendor: IR
Q15 Q16 Q20 Q21 Q27 Q28 Q32 Q35 Q36 Q47 Q49 = NMOS: AGILE_PN: 480-78399; MPN: IRLML6346TRPBF; TYPE: MOS; Vendor: IR
R904 = RES: AGILE_PN: 470-31071; TOL: 1%
R733 R905 = RES: AGILE_PN: 470-30858; TOL: 1%
R732 R740 R741 R750 R758 R759 R776 R777 R906 R910 R925 R927 R933 R934 = RES: BOM_IGNORE: DNP; TOL: 5%
R729 R731 R736 R738 R748 R749 R753 R757 R766 R767 R772 R774 R807 R907 R913 R914 R922 R924 R929 R937 = RES: AGILE_PN: 470-75416; TOL: 1%
R662 R663 R669 R671 R678 R679 R684 R685 R703 R704 R734 R737 R739 R752 R754 R756 R768 R770 R771 R773 R784 R786 R818 R819 R821 R831 R908 R916 R920 R931 R932 R947 R949 = RES: AGILE_PN: 470-75557; TOL: 5%
R656 R666 R670 R672 R673 R681 R682 R713 R782 R785 R815 R820 R830 R909 R919 R948 = RES: AGILE_PN: 470-75555; TOL: 5%
R659 R675 R676 R742 R743 R760 R761 R778 R779 R783 R816 R817 R911 R912 R918 R935 R936 R946 R983-R985 = RES: AGILE_PN: 470-75394; TOL: 5%
R915 = RES: AGILE_PN: 470-76255; TOL: 5%
R917 = RES: AGILE_PN: 470-30719; TOL: 1%
R921 = RES: AGILE_PN: 470-00155; TOL: 1%
R923 = RES: AGILE_PN: 470-31079; TOL: 1%
R926 = RES: AGILE_PN: 470-30864; TOL: 1%
R928 = RES: AGILE_PN: 470-30877; TOL: 1%
R930 = RES: AGILE_PN: 470-30962; TOL: 1%
R938 = RES: AGILE_PN: 470-30888; TOL: 1%
R980 = RES_PWR: AGILE_PN: 470-80370; MPN: WSL27261L000FEA; Vendor: Vishay
R694 R981 R982 = RES: AGILE_PN: 470-75589; TOL: 5%
U87 U90 U103 = IR3475: AGILE_PN: 315-80300; MPN: IR3475MTR1PBF; TYPE: IC; Vendor: IR
U104 = 74CBTLV1G125: AGILE_PN: 312-75769; MPN: SN74CBTLV1G125DCKR; TYPE: IC; Vendor: TI
U86 U88 U89 U91 U105 U106 = IR3475: AGILE_PN: 315-80499; MPN: IR3473MTR1PBF; TYPE: IC; Vendor: IR
U111 = INA220: AGILE_PN: 315-79035; MPN: INA220AIDGST; TYPE: IC; Vendor: TI
C942 = CAP: AGILE_PN: 150-75452; VOLTAGE: 50V
C967 = CAP: AGILE_PN: 150-00081; VOLTAGE: 50V
L19 L20 = IND_IRON: AGILE_PN: 180-75110; MPN: IHLP2525CZER3R3M01; TYPE: IND; Vendor: Vishay
R728 = RES: AGILE_PN: 470-31085; TOL: 1%
R730 = RES: AGILE_PN: 470-00152; TOL: 1%
R735 = RES: AGILE_PN: 470-30868; TOL: 1%
R744 = RES: AGILE_PN: 470-00153; TOL: 1%
R745 = RES: AGILE_PN: 470-30922; TOL: 1%
R746 = RES: AGILE_PN: 470-31090; TOL: 1%
R747 = RES: AGILE_PN: 470-31099; TOL: 1%
R751 = RES: AGILE_PN: 470-77279; TOL: 1%
R755 R780 = RES: AGILE_PN: 470-30876; TOL: 1%
R762 = RES: AGILE_PN: 470-30913; TOL: 1%
R763 = RES: AGILE_PN: 470-76087; TOL: 1%
R764 = RES: AGILE_PN: 470-31114; TOL: 1%
R765 = RES: AGILE_PN: 470-00112; TOL: 1%
R769 = RES: AGILE_PN: 470-30878; TOL: 1%
R775 = RES: AGILE_PN: 470-30873; TOL: 1%
R781 = RES: AGILE_PN: 470-30861; TOL: 1%
C880 C881 C1017 = CAP: AGILE_PN: 150-78675; VOLTAGE: 6.3V
C882 C1282 = CAP: AGILE_PN: 150-75487; VOLTAGE: 6.3V
C885 C886 = CAP: AGILE_PN: 150-30121; VOLTAGE: 6.3V
C887 = CAP: AGILE_PN: 150-76334; VOLTAGE: 50V
Q11 Q17 = NMOS_SO8FL: AGILE_PN: 480-00030; MPN: IRFHM4226TRPBF; TYPE: MOS; Vendor: IR
Q12 = PMOS_SO8: AGILE_PN: 480-00028; MPN: IRF9321TRPBF; TYPE: MOS; Vendor: IR
Q33 Q34 Q44 Q45 Q48 = NMOS: AGILE_PN: 480-78848; MPN: IRLML2030TRPBF; TYPE: MOS; Vendor: IR
Q37 Q38 = NMOS: AGILE_PN: 480-75173; TYPE: MOS; Vendor: IR
R695 R696 = RES: AGILE_PN: 470-76037; TOL: 1%
R697 R714 R715 = RES: AGILE_PN: 470-75597; TOL: 5%
R806 = RES: AGILE_PN: 470-30906; TOL: 1%
R705 R706 R708 R710 R712 R870 = RES: AGILE_PN: 470-75626; TOL: 5%
R945 = RES: AGILE_PN: 470-75642; TOL: 5%
U81 = TPS51200: AGILE_PN: 315-77573; MPN: TPS51200DRCT; TYPE: IC; Vendor: TI
U95 = MIC47100-MSOP8: AGILE_PN: 315-78329; MPN: MIC49150YMM; TYPE: IC; Vendor: Micrel
C890 C1278 C1279 = CAP: AGILE_PN: 150-77350; VOLTAGE: 25V
C891 C1280 = CAP: AGILE_PN: 150-75016; VOLTAGE: 25V
C892 = CAP: AGILE_PN: 150-75266; VOLTAGE: 50V
D33 = DIODE_SCHOTTKY: AGILE_PN: 480-00025; MPN: BAT43WS-7-F; TYPE: DIODE; Vendor: DIODES
D34 D35 = DIODE_SCHOTTKY: AGILE_PN: 480-75983; MPN: RB521S30T1G; TYPE: DIODE; Vendor: ON Semi
D43 D44 = LED: AGILE_PN: 370-00015; MPN: L-96A8YVP/1GD/TG-0L; Vendor: Kingbrignt
F9-F15 = PTC: BOM_IGNORE: DNP; MPN: 1206L050; Vendor: Littelfuse
J33 J34 J44-J46 J58 J59 = CONN_3PIN: AGILE_PN: 210-75442; MPN: WRFB-DS03T2NNAX-X; TYPE: HDR; Vendor: SUPERIOR TECH
J35 J47 J48 = CONN_1X2: AGILE_PN: 210-80733; MPN: TSW-102-07-F-S; TYPE: HDR; Vendor: Samtec
J37 = ATX_PWR_CONN_20PIN: AGILE_PN: 211-00037; MPN: 5566-20A; TYPE: CON; Vendor: MOLEX
L16 = IND_IRON: AGILE_PN: 180-00018; MPN: MDR43SG220M; TYPE: IND; Vendor: MNC
Q29 = NMOS: AGILE_PN: 480-30015; MPN: IRLML2502TRPBF; TYPE: MOS; Vendor: IR
Q30 = TRANS_NPN: AGILE_PN: 480-75087; MPN: MMBT4401-7-F; TYPE: TRAN; Vendor: DIODES
R699 R702 = RES: AGILE_PN: 470-80835; TOL: 5%
R700 R701 R861-R863 R986 R987 = RES: AGILE_PN: 470-75924; TOL: 5%
R707 R711 = RES: AGILE_PN: 470-30454; TOL: 5%
R709 = RES: AGILE_PN: 470-76218; TOL: 1%
SW4 SW5 = SWITCH_2P2: AGILE_PN: 510-00024; MPN: KFC-01-01-01-6*6*7; TYPE: CON; Vendor: UNIT
U83 = MAX811S: AGILE_PN: 312-79609; MPN: MIC811RUY; TYPE: IC; Vendor: Micrel
U84 = 74LVC2G74: AGILE_PN: 312-81109; MPN: SN74LVC2G74DCUR; TYPE: IC; Vendor: TI
U85 = 74LVC1G14: AGILE_PN: 312-81107; MPN: SN74AHC1G14DCKR; TYPE: IC; Vendor: TI
M19 = DDR_MDL: MPN: MT18KSF51272AZ-1G6; TYPE: MDL; Vendor: Micron
Z97-Z104 = FIDUCIAL: TYPE: PAD
Z105-Z112 = MH_M8: TYPE: PAD

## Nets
0V85: C933.1 C935.1 C937.1 C939.1 C1063.1 C1064.1 L17.2 R738.2 ; also on sheet 1 19
1V0S: C1017.1 C1079.1 R806.2 U95.7(OUT) U95.8(OUT) ; also on sheet 13
1V2: C1236.1 C1239.1 C1240.1 C1241.1 C1248.1 C1249.1 L24.2 R930.2 ; also on sheet 1 2 10 13 18 19
1V5: C959.1 C960.1 C961.1 C964.1 C1095.1 C1096.1 L19.2 R753.2 ; also on sheet 21
1V8: Q11.1 Q11.2 Q11.3 Q44.2(S) R656.2 ; also on sheet 6 7 8 9 13 14 22 23
1V8_SLP: C958.1 C962.1 C963.1 C965.1 C1015.1 C1097.1 C1098.1 L20.2 Q11.5 R757.2 U95.1(IN) U95.2(IN) ; also on sheet 9 13 14 22 23 24
1V35: Q31.1 Q31.2 Q31.3 R782.2 ; also on sheet 5 13 14
1V35_SLP: C880.1 C881.1 C934.1 C936.1 C940.1 C941.1 C1069.1 C1070.1 L18.2 Q31.5 R695.2 R736.2 U81.2(VLDOIN) ; also on sheet 5
2V1: C1237.1 C1238.1 C1242.1 C1243.1 C1252.1 C1253.1 L25.2 R929.2 ; also on sheet 1 19
2V5: Q17.1 Q17.2 Q17.3 R672.2 ; also on sheet 1 2 10 13 17 18 19 20
2V5_SLP: C982.1 C983.1 C984.1 C988.1 C1099.1 C1100.1 L21.2 Q17.5 R774.2 ; also on sheet 9 10 13 14 16
3V3: Q18.1 Q18.2 Q18.3 Q45.2(S) R673.2 ; also on sheet 7 8 9 11 12 13 15 17 21 23 24
3V3_PGOOD: R771.2 U90.3(PGOOD) ; also on sheet 22
3V3_SLP: C882.1 C985.1 C986.1 C987.1 C989.1 C1002.1 C1016.1 C1066.1 C1067.1 C1068.1 C1223.1 C1379.1 D43.2 D44.2 L22.2 Q18.5 R697.2 R703.2 R704.2 R705.2 R771.1 R772.2 U81.10(VIN) U83.4(VCC) U95.4(BIAS) U104.5(VCC) U111.6(VS) ; also on sheet 5 9 15 16 22
5V0_SB: C897.1 C898.1 J37.9(+5VSB) R710.2 R711.2 R715.1 U84.7(~{PRE}) U84.8(VCC) U85.5(VCC)
5V0_SLP: C925.1 C926.1 C928.2 C929.2 C930.1 C931.1 C950.2 C951.2 C952.1 C953.1 C954.1 C955.1 C973.2 C974.2 C975.1 C976.1 C979.1 C980.1 C1053.2 C1054.2 C1055.2 C1056.2 C1057.2 C1058.2 C1112.1 C1113.1 C1208.1 C1209.1 C1210.1 C1211.1 C1213.1 C1226.2 C1227.2 C1228.1 C1229.1 C1230.2 C1232.2 C1233.1 C1234.1 J37.4(+5VDC) J37.6(+5VDC) J37.19(+5VDC) J37.20(+5VDC) R706.2 R728.1 R730.1 R732.1 R734.1 R737.1 R739.1 R746.1 R747.1 R750.1 R752.1 R754.1 R756.1 R764.1 R765.1 R768.1 R770.1 R773.1 R904.1 R906.1 R908.1 R921.1 R923.1 R925.1 R927.1 R931.1 R932.1 U86.10(VCC) U86.13(VIN) U87.10(VCC) U87.13(VIN) U88.10(VCC) U88.13(VIN) U89.10(VCC) U89.13(VIN) U90.10(VCC) U90.13(VIN) U91.10(VCC) U91.13(VIN) U103.10(VCC) U103.13(VIN) U105.10(VCC) U105.13(VIN) U106.10(VCC) U106.13(VIN) ; also on sheet 12
12V: F9.1 F11.1 F12.1 F13.1 F14.1 F15.1 Q12.5 Q12.6 Q12.7 Q12.8 R700.1 R861.1 R862.1 R863.1 R870.2 R986.1 R987.1 ; also on sheet 11 21
12V_SLP: C874.1 C1278.1 C1279.1 C1280.1 C1281.1 F10.1 J37.10(+12VDC) Q12.1 Q12.2 Q12.3 R662.1 R663.1 R678.1 R679.1 R701.1 R784.1 R818.1 R819.2 R916.2 R947.1
-5VDC: J37.18(-5VDC)
-12VDC: J37.12(-12VDC)
GND: C873.1 C875.1 C876.1 C880.2 C881.2 C882.2 C883.2 C884.2 C885.2 C886.2 C887.2 C892.2 C893.2 C894.2 C895.2 C896.2 C897.2 C898.2 C925.2 C926.2 C928.1 C929.1 C930.2 C931.2 C932.1 C933.2 C934.2 C936.2 C937.2 C938.1 C939.2 C940.2 C944.2 C945.2 C946.2 C947.2 C950.1 C951.1 C952.2 C953.2 C954.2 C955.2 C956.1 C957.1 C958.2 C959.2 C960.2 C961.2 C962.2 C963.2 C968.2 C969.2 C970.2 C971.2 C973.1 C974.1 C975.2 C976.2 C977.1 C979.2 C980.2 C981.1 C982.2 C983.2 C984.2 C985.2 C986.2 C987.2 C992.2 C993.2 C994.2 C995.2 C996.1 C1002.2 C1015.2 C1016.2 C1017.2 C1023.1 C1024.2 C1053.1 C1054.1 C1055.1 C1056.1 C1057.1 C1058.1 C1063.2 C1064.2 C1066.2 C1067.2 C1068.2 C1069.2 C1070.2 C1079.2 C1095.2 C1096.2 C1097.2 C1098.2 C1099.2 C1100.2 C1112.2 C1113.2 C1208.2 C1209.2 C1210.2 C1211.2 C1212.1 C1213.2 C1215.2 C1216.2 C1217.2 C1218.2 C1220.2 C1221.2 C1222.2 C1223.2 C1226.1 C1227.1 C1228.2 C1229.2 C1230.1 C1231.1 C1232.1 C1233.2 C1234.2 C1235.1 C1236.2 C1237.2 C1238.2 C1240.2 C1241.2 C1242.2 C1246.2 C1247.2 C1248.2 C1249.2 C1250.2 C1251.2 C1252.2 C1253.2 C1273.1 C1278.2 C1279.2 C1280.2 C1281.2 C1282.2 C1283.2 C1284.2 C1379.2 J33.1 J33.3 J35.2 J37.3(COM) J37.5(COM) J37.7(COM) J37.13(COM) J37.15(COM) J37.16(COM) J37.17(COM) J44.1 J44.3 J45.1 J45.3 J46.1 J46.3 J47.2 J48.2 J58.1 J58.3 J59.1 J59.3 Q15.2(S) Q16.2(S) Q20.2(S) Q21.2(S) Q27.2(S) Q28.2(S) Q29.2(S) Q30.2(E) Q32.2(S) Q35.2(S) Q36.2(S) Q37.2(S) Q38.2(S) Q47.2(S) Q49.2(S) R656.1 R669.1 R671.1 R672.1 R673.1 R684.1 R685.1 R696.1 R699.1 R708.1 R712.1 R742.1 R743.1 R744.1 R745.1 R760.1 R761.1 R762.1 R763.1 R778.1 R779.1 R780.1 R781.1 R782.1 R786.1 R807.1 R815.1 R821.1 R831.1 R870.1 R909.1 R911.1 R913.1 R920.1 R935.1 R936.1 R937.1 R938.1 R945.1 R949.1 R983.1 R984.1 SW4.1 SW4.3 SW4.4 SW5.1 SW5.3 SW5.4 U81.4(PGND) U81.8(GND) U81.11(PAD) U83.1(GND) U84.4(GND) U85.3(GND) U86.4(GND) U86.11(PGND) U86.17(GND) U87.4(GND) U87.11(PGND) U87.17(GND) U88.4(GND) U88.11(PGND) U88.17(GND) U89.4(GND) U89.11(PGND) U89.17(GND) U90.4(GND) U90.11(PGND) U90.17(GND) U91.4(GND) U91.11(PGND) U91.17(GND) U95.3(GND) U95.9(EPAD) U103.4(GND) U103.11(PGND) U103.17(GND) U104.3(GND) U105.4(GND) U105.11(PGND) U105.17(GND) U106.4(GND) U106.11(PGND) U106.17(GND) U111.7(GND) Z105.1 Z105.2 Z105.3 Z105.4 Z105.5 Z105.6 Z105.7 Z105.8 Z106.1 Z106.2 Z106.3 Z106.4 Z106.5 Z106.6 Z106.7 Z106.8 Z109.1 Z109.2 Z109.3 Z109.4 Z109.5 Z109.6 Z109.7 Z109.8 Z110.1 Z110.2 Z110.3 Z110.4 Z110.5 Z110.6 Z110.7 Z110.8 Z111.1 Z111.2 Z111.3 Z111.4 Z111.5 Z111.6 Z111.7 Z111.8 Z112.1 Z112.2 Z112.3 Z112.4 Z112.5 Z112.6 Z112.7 Z112.8 ; also on sheet 1 2 5 6 7 8 9 10 11 12 13 14 15 16 17 18 19 20 21 22 23 24
VDD_EN: U95.5(EN) ; also on sheet 22
VDD_EN_N: R919.1 ; also on sheet 22
CKE_ISO_EN: R830.1 ; also on sheet 22
DDR_MCKE0: Q37.3(D) ; also on sheet 5
DDR_MCKE1: Q38.3(D) ; also on sheet 5
DDRPWR_EN: U81.7(EN) ; also on sheet 22
DDRPWR_EN_N: R785.1 R948.1 ; also on sheet 22
EARTH: Z107.1 Z107.2 Z107.3 Z107.4 Z107.5 Z107.6 Z107.7 Z107.8 Z108.1 Z108.2 Z108.3 Z108.4 Z108.5 Z108.6 Z108.7 Z108.8 ; also on sheet 12 15 16 17 20
EVDD: C1282.1 C1283.1 C1284.1 Q33.2(S) Q34.2(S) R815.2 ; also on sheet 8 13
EVDD_SEL: R820.1 ; also on sheet 22
FAN_PWM: Q27.1(G) ; also on sheet 22
I2C1_SCL_SLP: U111.5(SCL) ; also on sheet 5 9 15 24
I2C1_SDA_SLP: U111.4(SDA) ; also on sheet 5 9 15 24
INA_VCORE_N: C1378.2 R982.1 U111.9(VIN-)
INA_VCORE_P: C1378.1 R981.1 U111.10(VIN+)
IOPWR_EN: C938.2 C956.2 C1231.2 C1235.2 R670.1 R732.2 R750.2 R925.2 R927.2 U86.16(EN) U88.16(EN) U105.16(EN) U106.16(EN) ; also on sheet 22
IOPWR_EN_N: R666.1 R681.1 R682.1 ; also on sheet 22
LED_STATUS: R702.1 ; also on sheet 22
MVREF: Q48.2(S) R945.2 ; also on sheet 5
MVREF_SLP: C883.1 Q48.3(D) U81.6(REFOUT) ; also on sheet 5
PWR_EN_N: J37.14(~{PS_ON}) J48.1 Q30.3(C) R710.1
PWR_GOOD: C894.1 R709.1 R712.2 ; also on sheet 22
PWR_RST_N: R708.2 U83.2(~{RESET}) ; also on sheet 22
SENSEVDD: R918.1 ; also on sheet 13
SENSEVDD_EN_N: U104.1(~{OE}) ; also on sheet 22
SENSEVDDC: R917.1 ; also on sheet 13
THERM_FAULT_N: D34.1 ; also on sheet 15 22
VCORE: Q46.1 Q46.2 Q46.3 R909.2 ; also on sheet 13 14
VCORE_EN: C1212.2 R906.2 U103.16(EN) ; also on sheet 22
VCORE_SLP: Q46.5 R980.4 ; also on sheet 13
VTT: C885.1 C886.1 R694.2 U81.3(VO) ; also on sheet 5
N17399246: C893.1 R705.1 R707.2 U83.3(~{MR})
N17399288: J47.1 R707.1 SW4.2
N17400346: D35.2 R711.1 R714.1 SW5.2
N17401317: U84.1(CLK) U85.4(O)
N17401544: C895.1 D35.1 R714.2 U85.2(I)
N17403382: C890.2 C891.2 J34.1 J34.3 J35.1 L16.2
N17403388: C890.1 C891.1 D33.1 F10.2 J34.2 R701.2
N17523688: U84.2(D) U84.3(~{Q})
N17523697: R713.1 U84.5(Q)
N17523706: C896.1 R715.2 U84.6(~{CLR})
N17523733: D33.2 L16.1 Q29.3(D)
N17524661: C892.1 Q28.3(D) Q29.1(G) R704.1
N17525004: D34.2 Q27.3(D) Q28.1(G) R703.1
N18263878: R904.2 U103.15(FF)
N18263905: C1220.1 R910.1 U103.8(3VCBP)
N18263955: R910.2 R911.2 U103.1(FCCM)
N18263961: C1207.2 L23.1 R905.1 R907.2 U103.12(PHASE)
N18263987: C1214.1 C1219.1 R905.2
N18264005: C1214.2 C1215.1 C1216.1 C1217.1 C1218.1 L23.2 R915.2 R980.1
N18264015: C1219.2 R913.2 R914.2 U103.5(FB)
N18264194: R908.2 U103.3(PGOOD)
N18264460: C1221.1 U103.6(SS)
N18264464: C1207.1 U103.14(BOOT)
N18264487: R907.1 U103.2(ISET)
N18271716: Q15.1(G) R666.2 R669.2
N18271718: C873.2 Q15.3(D) R659.2 R662.2
N18271794: Q11.4 R659.1
N18272820: C875.2 Q20.3(D) R675.2 R678.2
N18272822: Q20.1(G) R681.2 R684.2
N18272905: Q17.4 R675.1
N18273179: Q21.1(G) R682.2 R685.2
N18273181: C876.2 Q21.3(D) R676.2 R679.2
N18273262: Q18.4 R676.1
N18273767: Q16.1(G) R670.2 R671.2
N18273907: C874.2 Q12.4 Q16.3(D) R663.2
N18275087: C887.1 R695.1 R696.2 U81.1(REFIN)
N18275123: C884.1 R694.1 U81.5(VOSNS)
N18275169: R697.1 U81.9(PGOOD)
N18562864: Q30.1(B) R713.2
N18563122: J37.8(PWR_OK) R706.1 R709.2
N18583652: R918.2 U104.2(A)
N18583655: R914.1 R915.1 R917.2 R985.2 U104.4(B)
N19623883: C996.2 Q32.3(D) R783.2 R784.2
N19623885: Q32.1(G) R785.2 R786.2
N19623968: Q31.4 R783.1
N19644915: C927.2 L18.1 R731.2 R735.1 U87.12(PHASE)
N19644936: C941.2 C943.2 R735.2
N19644956: C943.1 R736.1 R745.2 U87.5(FB)
N19644972: R739.2 U87.3(PGOOD)
N19644986: C932.2 R734.2 U87.16(EN)
N19645019: C946.1 R741.1 U87.8(3VCBP)
N19645035: R741.2 R743.2 U87.1(FCCM)
N19645080: C947.1 U87.6(SS)
N19645160: R728.2 U87.15(FF)
N19645192: C927.1 U87.14(BOOT)
N19645200: R731.1 U87.2(ISET)
N19646811: C949.2 L20.1 R749.2 R755.1 U89.12(PHASE)
N19646830: C965.2 C967.2 R755.2
N19646848: C967.1 R757.1 R763.2 U89.5(FB)
N19646866: R749.1 U89.2(ISET)
N19646870: R756.2 U89.3(PGOOD)
N19646891: C957.2 R754.2 U89.16(EN)
N19646930: C970.1 R759.1 U89.8(3VCBP)
N19646940: R759.2 R761.2 U89.1(FCCM)
N19646995: C971.1 U89.6(SS)
N19647070: R747.2 U89.15(FF)
N19647102: C949.1 U89.14(BOOT)
N19648273: C978.2 L22.1 R767.2 R775.1 U90.12(PHASE)
N19648275: C989.2 C991.2 R775.2
N19648310: C991.1 R772.1 R781.2 U90.5(FB)
N19648328: R767.1 U90.2(ISET)
N19648366: C981.2 R770.2 U90.16(EN)
N19648414: C994.1 R777.1 U90.8(3VCBP)
N19648420: R777.2 R779.2 U90.1(FCCM)
N19648465: C995.1 U90.6(SS)
N19648544: R765.2 U90.15(FF)
N19648572: C978.1 U90.14(BOOT)
N19650144: C972.2 L21.1 R766.2 R769.1 U91.12(PHASE)
N19650163: C988.2 C990.2 R769.2
N19650181: C990.1 R774.1 R780.2 U91.5(FB)
N19650199: R766.1 U91.2(ISET)
N19650212: R773.2 U91.3(PGOOD)
N19650233: C977.2 R768.2 U91.16(EN)
N19650272: C992.1 R776.1 U91.8(3VCBP)
N19650282: R776.2 R778.2 U91.1(FCCM)
N19650331: C993.1 U91.6(SS)
N19650402: R764.2 U91.15(FF)
N19650430: C972.1 U91.14(BOOT)
N19651609: C948.2 L19.1 R748.2 R751.1 U88.12(PHASE)
N19651628: C964.2 C966.2 R751.2
N19651646: C966.1 R753.1 R762.2 U88.5(FB)
N19651664: R748.1 U88.2(ISET)
N19651683: R752.2 U88.3(PGOOD)
N19651731: C968.1 R758.1 U88.8(3VCBP)
N19651747: R758.2 R760.2 U88.1(FCCM)
N19651788: C969.1 U88.6(SS)
N19651863: R746.2 U88.15(FF)
N19651895: C948.1 U88.14(BOOT)
N19653096: C924.2 L17.1 R729.2 R733.1 U86.12(PHASE)
N19653107: C935.2 C942.2 R733.2
N19653133: C942.1 R738.1 R744.2 U86.5(FB)
N19653151: R729.1 U86.2(ISET)
N19653170: R737.2 U86.3(PGOOD)
N19653218: C944.1 R740.1 U86.8(3VCBP)
N19653234: R740.2 R742.2 U86.1(FCCM)
N19653275: C945.1 U86.6(SS)
N19653350: R730.2 U86.15(FF)
N19653382: C924.1 U86.14(BOOT)
N20366563: R806.1 R807.2 U95.6(FB/ADJ)
N20553507: Q37.1(G) Q38.1(G) R830.2 R831.2
N20559490: Q35.1(G) R820.2 R821.2
N20559492: C1023.2 Q35.3(D) Q36.1(G) R816.2 R818.2
N20559589: Q33.1(G) Q44.1(G) R816.1
N20559634: Q33.3(D) Q44.3(D)
N20559669: C1024.1 Q36.3(D) R817.1 R819.1
N20559724: Q34.1(G) Q45.1(G) R817.2
N22360230: F9.2 J33.2 R700.2
N22360382: F11.2 J44.2 R861.2
N22360534: F12.2 J45.2 R862.2
N22361017: F13.2 J46.2 R863.2
N22361656: D43.1 R702.2
N22361689: D44.1 R699.2
N22440478: Q34.3(D) Q45.3(D)
N23395649: C1224.2 L24.1 R922.2 R926.1 U105.12(PHASE)
N23395651: C1239.2 C1244.2 R926.2
N23395686: C1244.1 R930.1 R937.2 U105.5(FB)
N23395694: R922.1 U105.2(ISET)
N23395911: C1224.1 U105.14(BOOT)
N23398740: R931.2 U105.3(PGOOD)
N23398788: C1246.1 R933.1 U105.8(3VCBP)
N23398805: R933.2 R935.2 U105.1(FCCM)
N23398854: C1247.1 U105.6(SS)
N23398896: R923.2 U105.15(FF)
N23399971: C1225.2 L25.1 R924.2 R928.1 U106.12(PHASE)
N23399992: C1243.2 C1245.2 R928.2
N23400010: C1245.1 R929.1 R938.2 U106.5(FB)
N23400026: R924.1 U106.2(ISET)
N23400036: R932.2 U106.3(PGOOD)
N23400099: C1250.1 R934.1 U106.8(3VCBP)
N23400105: R934.2 R936.2 U106.1(FCCM)
N23400150: C1251.1 U106.6(SS)
N23400230: R921.2 U106.15(FF)
N23400248: C1225.1 U106.14(BOOT)
N23495851: Q49.1(G) R948.2 R949.2
N23495853: C1273.2 Q49.3(D) R946.2 R947.2
N23495929: Q48.1(G) R946.1
N23926306: Q46.4 R912.2
N23926329: C1222.1 Q47.3(D) R912.1 R916.1
N23926341: Q47.1(G) R919.2 R920.2
N23927707: R980.2 R981.2
N23927714: R980.3 R982.2
N23928633: R983.2 U111.2(A0)
N23928636: R984.2 U111.1(A1)
N23929117: R985.1 U111.8(VBUS)
N24071716: F14.2 J58.2 R986.2
N24071917: F15.2 J59.2 R987.2

Not connected (* = marked no-connect by the designer): J37 1(+3.3VDC) 2(+3.3VDC) 11(+3.3VDC); U85 1(NC)*; U86 7(NC1)* 9(NC2)*; U87 7(NC1)* 9(NC2)*; U88 7(NC1)* 9(NC2)*; U89 7(NC1)* 9(NC2)*; U90 7(NC1)* 9(NC2)*; U91 7(NC1)* 9(NC2)*; U103 7(NC1)* 9(NC2)*; U105 7(NC1)* 9(NC2)*; U106 7(NC1)* 9(NC2)*; U111 3(NC)*; Z97 1*; Z98 1*; Z99 1*; Z100 1*; Z101 1*; Z102 1*; Z103 1*; Z104 1*

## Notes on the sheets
sheet 25
- T1024 CORE POWER CONVERTOR and SYSTEM POWER CONVERTORs
- Caution: separate analog and power ground and make connection at GND plane
- COPPER ISLAND
- COPPER PLANE
- Rff(kohm) = Vout/(1Vx20pFxFsw)
- 1.0uH(IHLP2525CZER1R0M01): Irms = 11A, Isat = 22A, DCR = 9mohm
- COPPER PLANE
- Fsw = 400KHz
- Vout = 0.5x(Rtop/Rbot+1)
- Rset = 13(mohm)xIoc/19(uA)
- DISCHARGE LOAD
- Enable DCM Mode
- Css(nF) = 22xTss(mS)
- I2C ADDR = 0x40
- 5~7 ohm on-state switch resistance
- COPPER ISLAND
- COPPER ISLAND
- Rff(kohm) = Vout/(1Vx20pFxFsw)
- SWITCHABLE
- COPPER PLANE
- Rff(kohm) = Vout/(1Vx20pFxFsw)
- SWITCHABLE
- COPPER PLANE
- Fsw = 400KHz
- Rset = 24(mohm)xIoc/19(uA)
- Fsw = 400KHz
- Rset = 24(mohm)xIoc/19(uA)
- Vout = 0.5x(Rtop/Rbot+1)
- Vout = 0.5x(Rtop/Rbot+1)
- Enable DCM Mode
- Enable DCM Mode
- Css(nF) = 22xTss(mS)
- Css(nF) = 22xTss(mS)
sheet 26
- SYSTEM POWER CONVERTORs
- 2.2uH(IHLP2525CZER2R2M01): Irms = 8A, Isat = 14A, DCR = 18mohm
- 3.3uH(IHLP2525CZER3R3M01): Irms = 6A, Isat = 13.5A, DCR = 28mohm
- COPPER ISLAND
- 4.7uH(IHLP2525CZER4R7M01): Irms = 5.5A, Isat = 10A, DCR = 37mohm
- COPPER ISLAND
- MAX 10A
- Rff(kohm) = Vout/(1Vx20pFxFsw)
- SWITCHABLE
- COPPER PLANE
- Rff(kohm) = Vout/(1Vx20pFxFsw)
- ALWAYS ON
- COPPER PLANE
- Fsw = 400KHz
- Rset = 24(mohm)xIoc/19(uA)
- Fsw = 400KHz
- Rset = 13(mohm)xIoc/19(uA)
- Vout = 0.5x(Rtop/Rbot+1)
- Vout = 0.5x(Rtop/Rbot+1)
- Enable DCM Mode
- Enable DCM Mode
- Css(nF) = 22xTss(mS)
- 1V35 POWER ON LAST
- Css(nF) = 22xTss(mS)
- COPPER ISLAND
- COPPER ISLAND
- Rff(kohm) = Vout/(1Vx20pFxFsw)
- SWITCHABLE
- COPPER PLANE
- Rff(kohm) = Vout/(1Vx20pFxFsw)
- ALWAYS ON
- COPPER PLANE
- Fsw = 400KHz
- Rset = 24(mohm)xIoc/19(uA)
- Fsw = 400KHz
- Rset = 24(mohm)xIoc/19(uA)
- Vout = 0.5x(Rtop/Rbot+1)
- Vout = 0.5x(Rtop/Rbot+1)
- Enable DCM Mode
- Enable DCM Mode
- Css(nF) = 22xTss(mS)
- Css(nF) = 22xTss(mS)
- COPPER ISLAND
- COPPER ISLAND
- MAX 10A
- Rff(kohm) = Vout/(1Vx20pFxFsw)
- ALWAYS ON
- COPPER PLANE
- Rff(kohm) = Vout/(1Vx20pFxFsw)
- ALWAYS ON
- COPPER PLANE
- Fsw = 400KHz
- Rset = 24(mohm)xIoc/19(uA)
- Fsw = 400KHz
- Rset = 13(mohm)xIoc/19(uA)
- Vout = 0.5x(Rtop/Rbot+1)
- Vout = 0.5x(Rtop/Rbot+1)
- Enable DCM Mode
- Enable DCM Mode
- Css(nF) = 22xTss(mS)
- Css(nF) = 22xTss(mS)
- Caution: separate analog and power ground and make connection at GND plane
sheet 27
- SYSTEM POWER SWITCHs
- DISCHARGE LOAD
- DISCHARGE LOAD
- DISCHARGE LOAD
- DISCHARGE LOAD
- DISCHARGE LOAD
- DISCHARGE LOAD
- COPPER ISLAND
- COPPER ISLAND
- DISCHARGE LOAD
- Vout = 0.7x(Rtop/Rbot+1)
- SVDD power on with VDD
sheet 28
- SYSTEM POWER INPUT
- CHASSIS FAN HEADER
- AQR105 FAN HEADER
- LABEL = SYS_FAN
- LABEL = XGT1_FAN
- LED
- LABEL = SYS_FAN
- LABEL = XGT2_FAN
- LABEL = SYS_FAN
- CPU FAN HEADER
- LABEL = SYS_FAN
- LABEL = CPU_FAN
- LABEL = FULL SPEED
- INSTALL JUMPER FOR
  FULL SPEED ON FAN
- ATX POWER INPUT CONNECTOR
- 5V MAX: 6A
  12V MAX: 3A
- LOCAL RESET
- LABEL = RESET
- REMOTE POWER
- LABEL = POWER
- LABEL = RESET
- REMOTE RESET
- PWR SWITCH
- LABEL = POWER
- 10mS Debounce
- Default Power Off
sheet 29
- MECHANICALs
- Fiducial Marks
- Layer Detail
- Top
- 1.5OZ
- L2GND
- 1OZ
- L3SIG
- 1OZ
- L4PWR
- 1OZ
- 2.0mm
  +/- 10%
- Mouting Holes
- L5PWR
- 1OZ
- L6SIG
- 1OZ
- L7GND
- 1OZ
- Bottom
- 1.5OZ
- Micron MPN(4GB,1600): MT18KSF51272AZ-1G6
sheet 30
- CHANGE LIST
- 2014/5/19
  1. Change T1040 part value to T1024
  2. Add AQ2104 JTAG connector for boundry-scan
  3. Change T1024 DDR power to be switched off in deep sleep mode (include D1-MVREF, GVDD, AVDD-D1)
  4. Change DDR3 SPD power from 3V3 to 3V3_SLP
  5. Mount R802,R803,R804 20K pull-up resistors
  6. Add NOR Flash RDY/BUSY signal to CPLD
  7. Connect SD card VDD pin to EVDD and correct C38, C39 power also
  8. Change R158,R159 from 10K to 100K, make R155,R156 as DNP
  9. Float pin1 of U38 and U96
  10. Add one 3000pF capacitor on 1V0_USB_SVDD
  11. Add power filter for G12 pin as AVDD_CGA2 of T1040
  12. Change I2C thermal monitor power supply from 3V3 to 3V3_SLP
  13. Add pull-up resistor for RTC_INT_N
  14. Change EC1 RJ45 LED connection as EC2, so EC1 PHY address change to 0x02 and EC2 PHY address change to 0x06
  15. Add EC1_PME_N connect to IRQ3
  16. Change C336,C342,C306,C310,C1205,C1206 to 1000pF, 2KV cap
  17. Add pull-up to XGT_SPI_CS_N
  18. Add 3pin debug header for AQ2104 SMBUS
  19. Add AC coupling capacitors on PCIe RX lines for safe
  20. Change CPLD power OVDD_SLP to 1V8_SLP
  21. Add 2pin Jumper for EVDD manual selection
  22. Add X1 and X5 OE control from SYSCLK_OE signal
  23. Change R938 to 3.09K to make 2.1V out put and correct C1252,C1253 power connection
  24. Correct R916 connection from 12V_M to 12V_SLP
  25. Change R744 to 14.3K to make 0.85V out put and correct C1063,C1064 power connection
  26. Remove jumper for DDR3 1.5V power support
  2014/5/26
  1. Change USB power switch from MIC2506YM to MAX1558H
  2. Change AQ2104 SPI flash AT45DB041D to MX25V4006E
  2014/5/27
  1. Change TVDD connect to 1V2, TVDD can be off in deep sleep mode
  2014/6/1
  1. Change NAND flash to 1.8V BGA NAND
  2. change 2 USB protect IC to 1 for cost saving
  2014/6/6
  1. Change SD card VDD select by 3pin Jumper, and add sense to CPLD
  2. Add all switch signals to CPLD
  2014/7/2
  1. Add more capacitors for EVDD
  2014/7/4
  1. Add beads for 2xGE port RJ45 LED signals
- 2014/9/18
  1. Change AQ2104 to AQR105, add another AQR105 for 2.5G SGMII
  2. Add serdes mux for PCIe and 2.5G SGMII
  3. Add VCORE power measurement
- 2014/9/28
  1. Change the title from 10G Base-T to 2.5G Base-T for second AQR105
  2. Correct the comments above the SerDes TX pair to Lane2 used for 2.5G SGMII Mode to MAC
  3. Change the signal names for 2 AQR105 JTAG and SPI to XGT1_xxx and XGT2_xxx
  4. Add all XREFs for missing XREF signals
  5. Add 1x1 header near VDD_SD 1x3 header for VDD_SD to connect to EVDD
  6. Add 2 fan header for AQR105
- 2014/10/8
  1. Remove C1195+C1196 and C1363+C1364 from CT of the magnetics, Change 2.2uF to 0.1uF per CT pin
  2. Add a EMI2 header for debug
  3. Add ferrite bead for AQR105 V22_SRDS power rails
  4. Change FB57, FB65 to MPZ2012S101A
  5. Change AQR105 SMB debug header pin order per reference design
- 2014/11/26
  1. Add 2 clock mux for SD1/2_REFCLK selection
  2. Change T1040 debug version resistors "V40" to "DNP"
